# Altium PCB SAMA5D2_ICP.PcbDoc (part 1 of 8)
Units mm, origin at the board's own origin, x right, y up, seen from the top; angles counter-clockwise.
Board outline 150 x 100 mm, 6 copper layers (L1 - TOP, L2 - GND, L3 - SIG, L4 - SIG, L5 - VCC, L6 - BOT), stack 1.512 mm thick; 708 components, 597 nets, 2710 pads, 1437 vias.
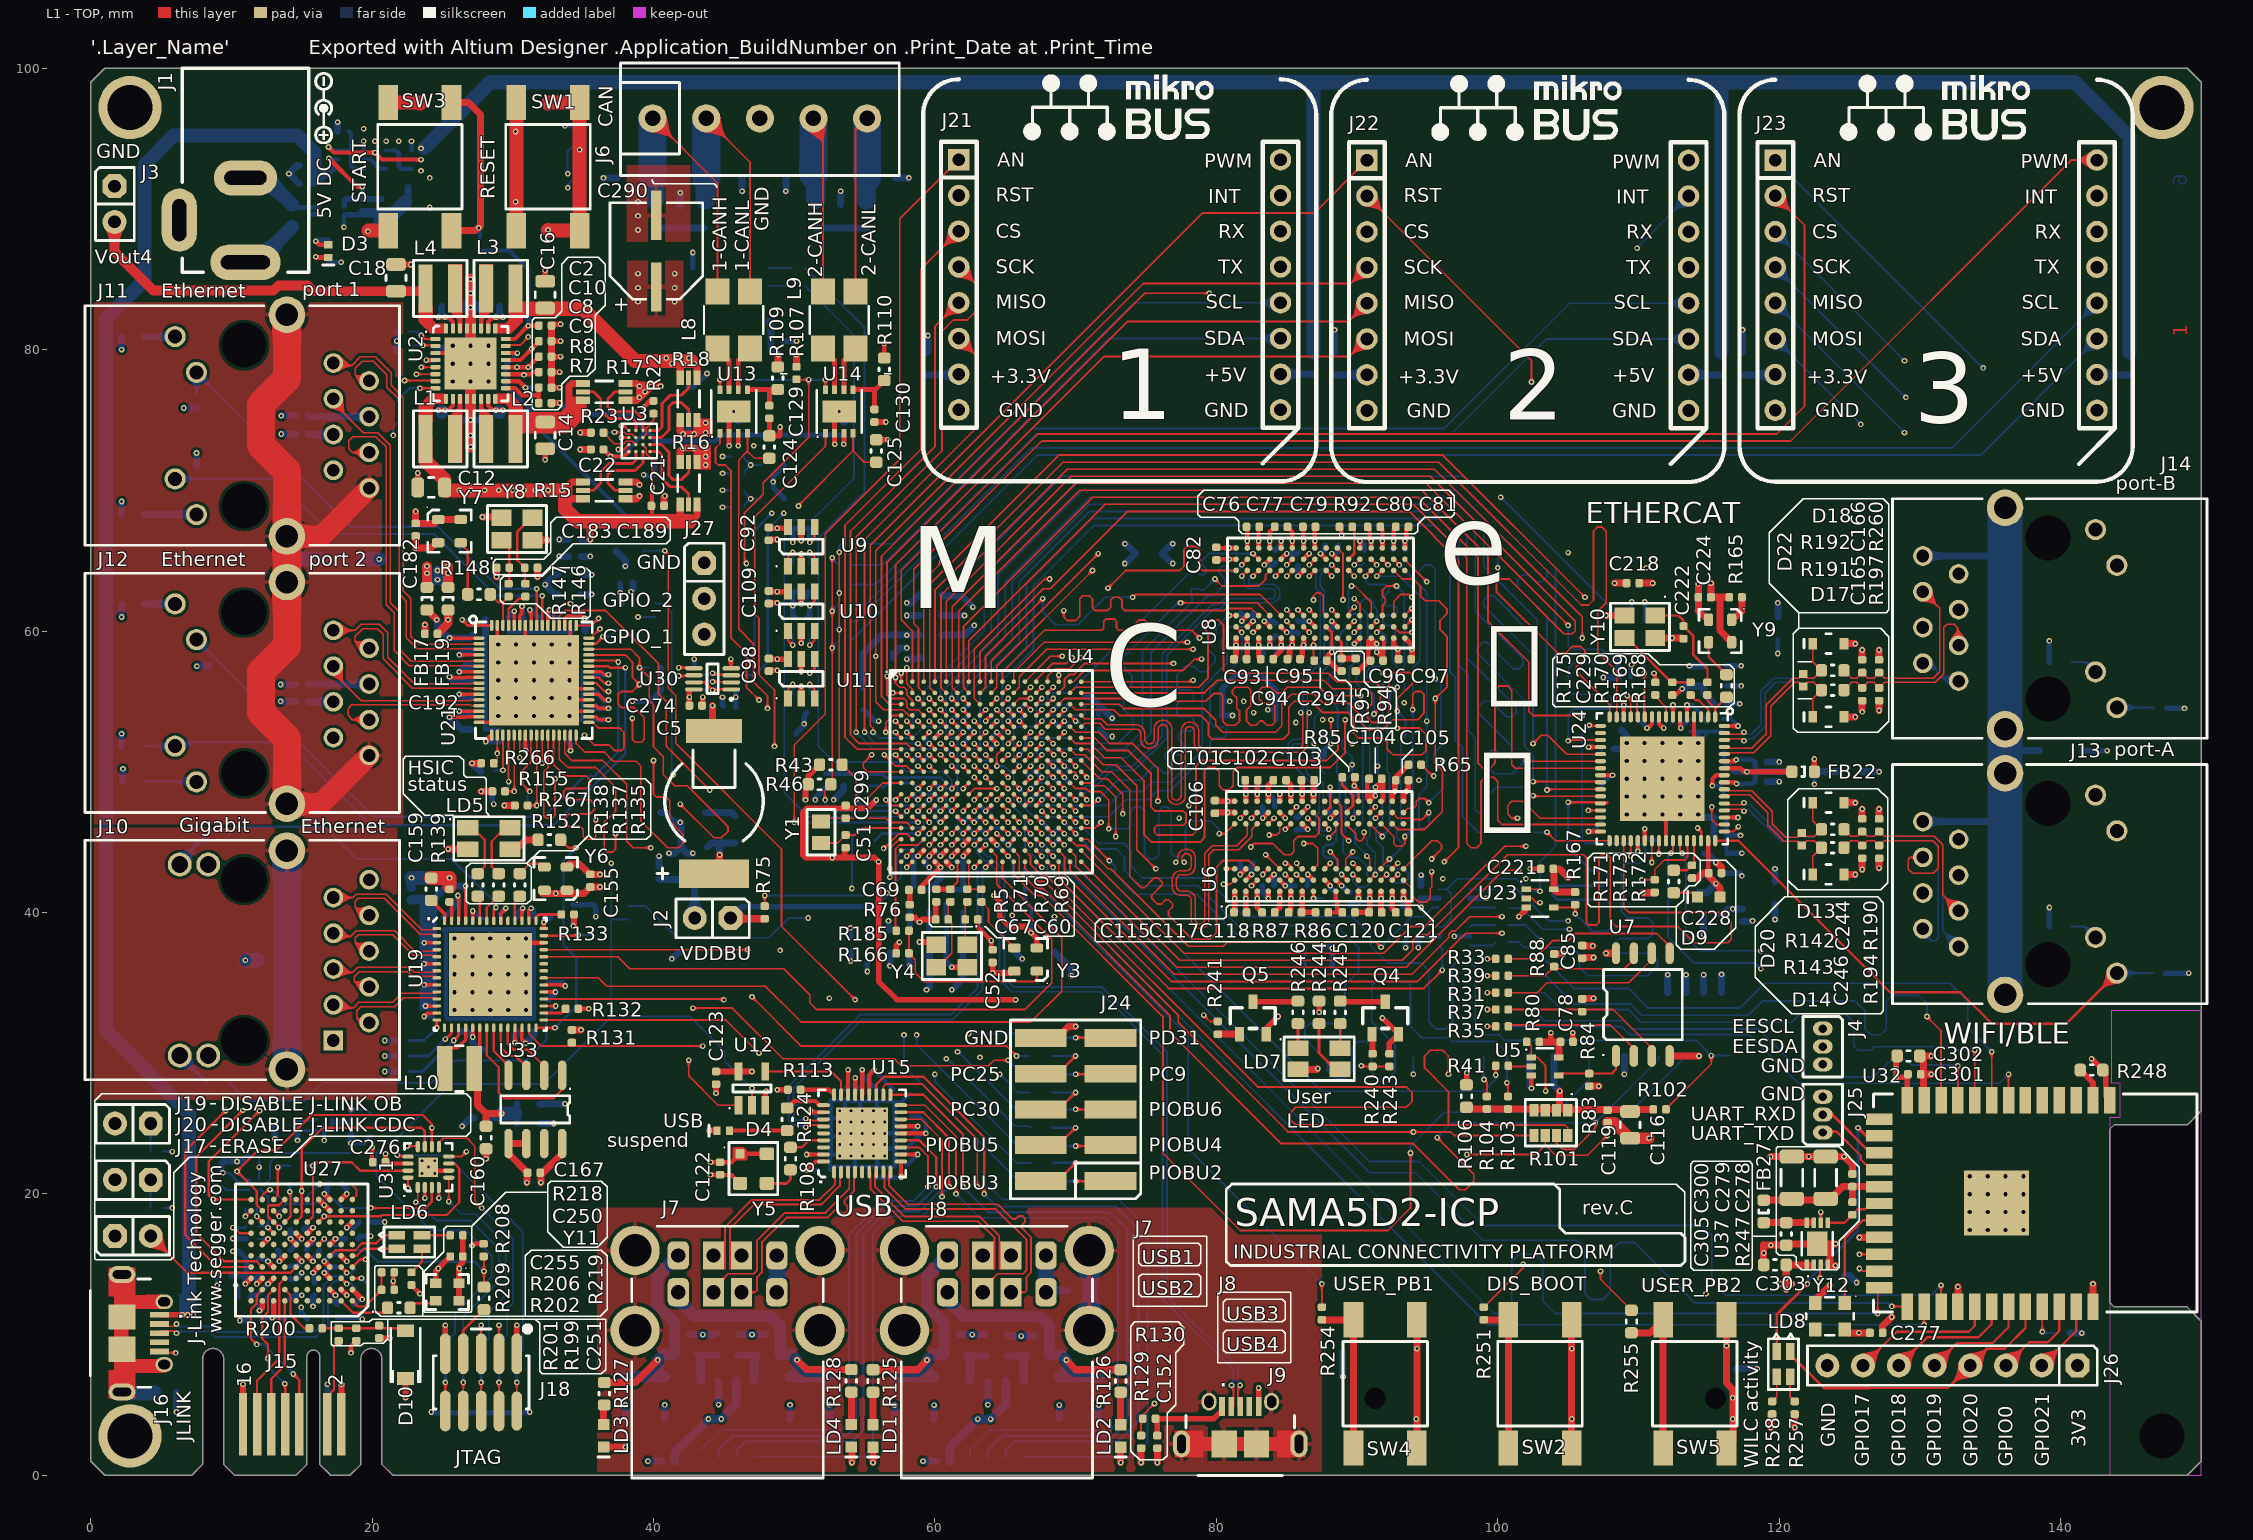
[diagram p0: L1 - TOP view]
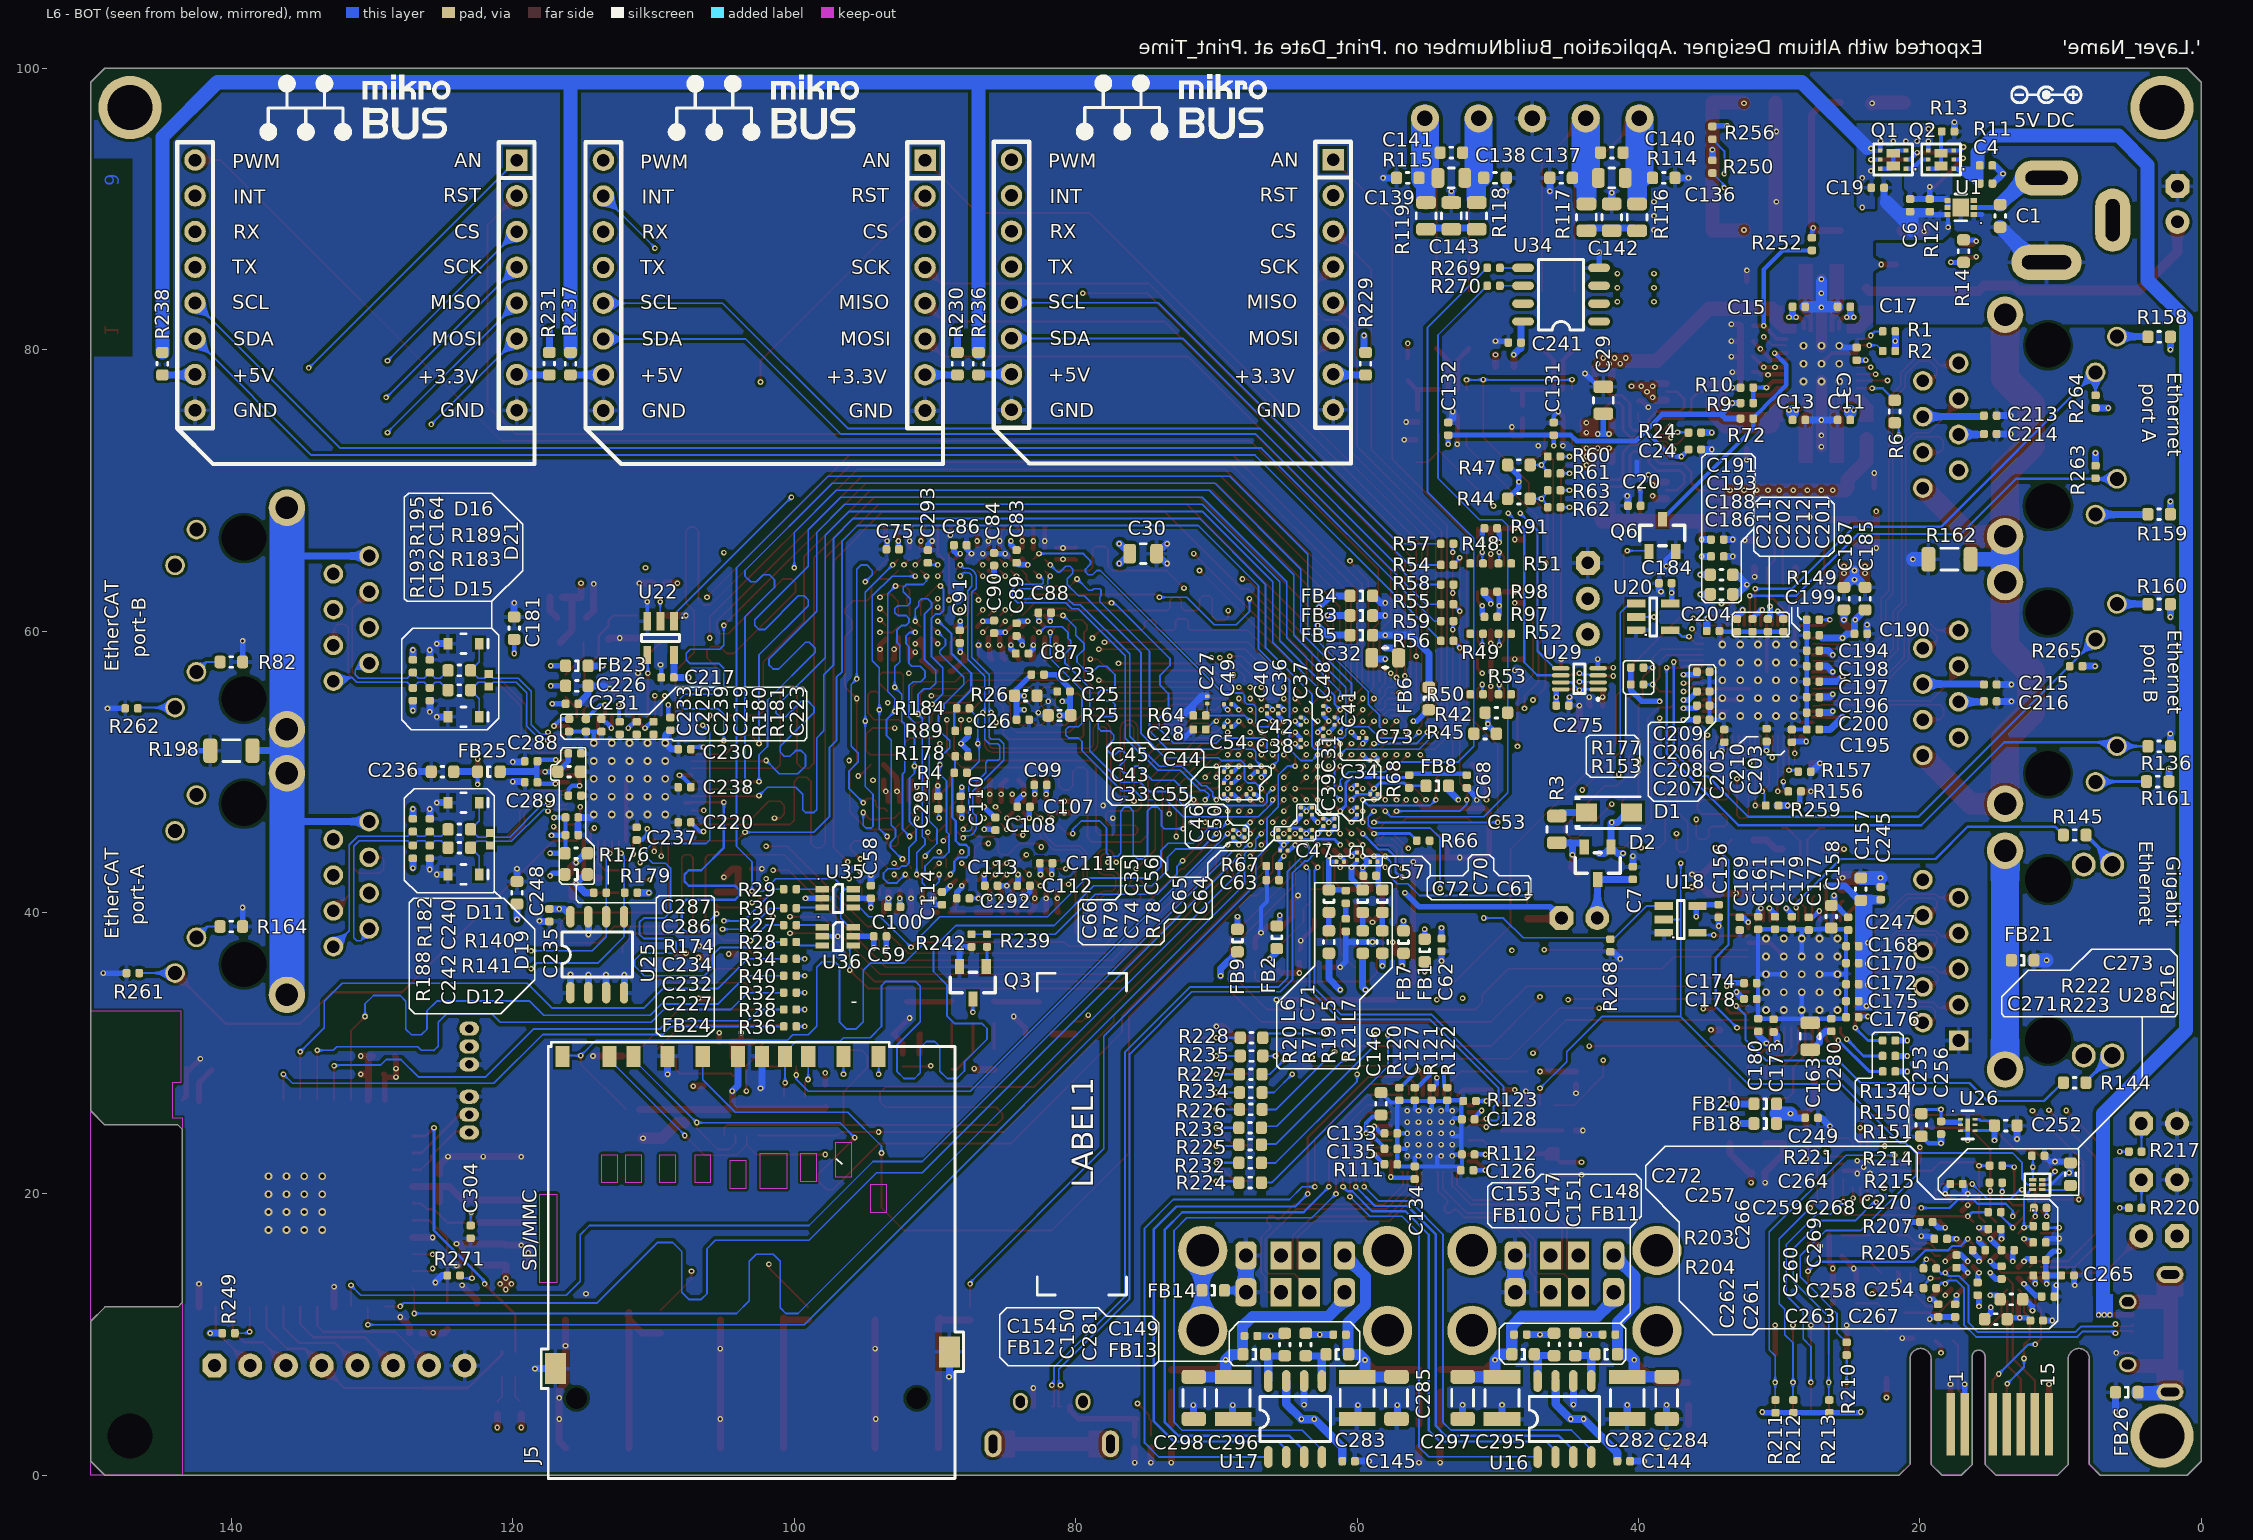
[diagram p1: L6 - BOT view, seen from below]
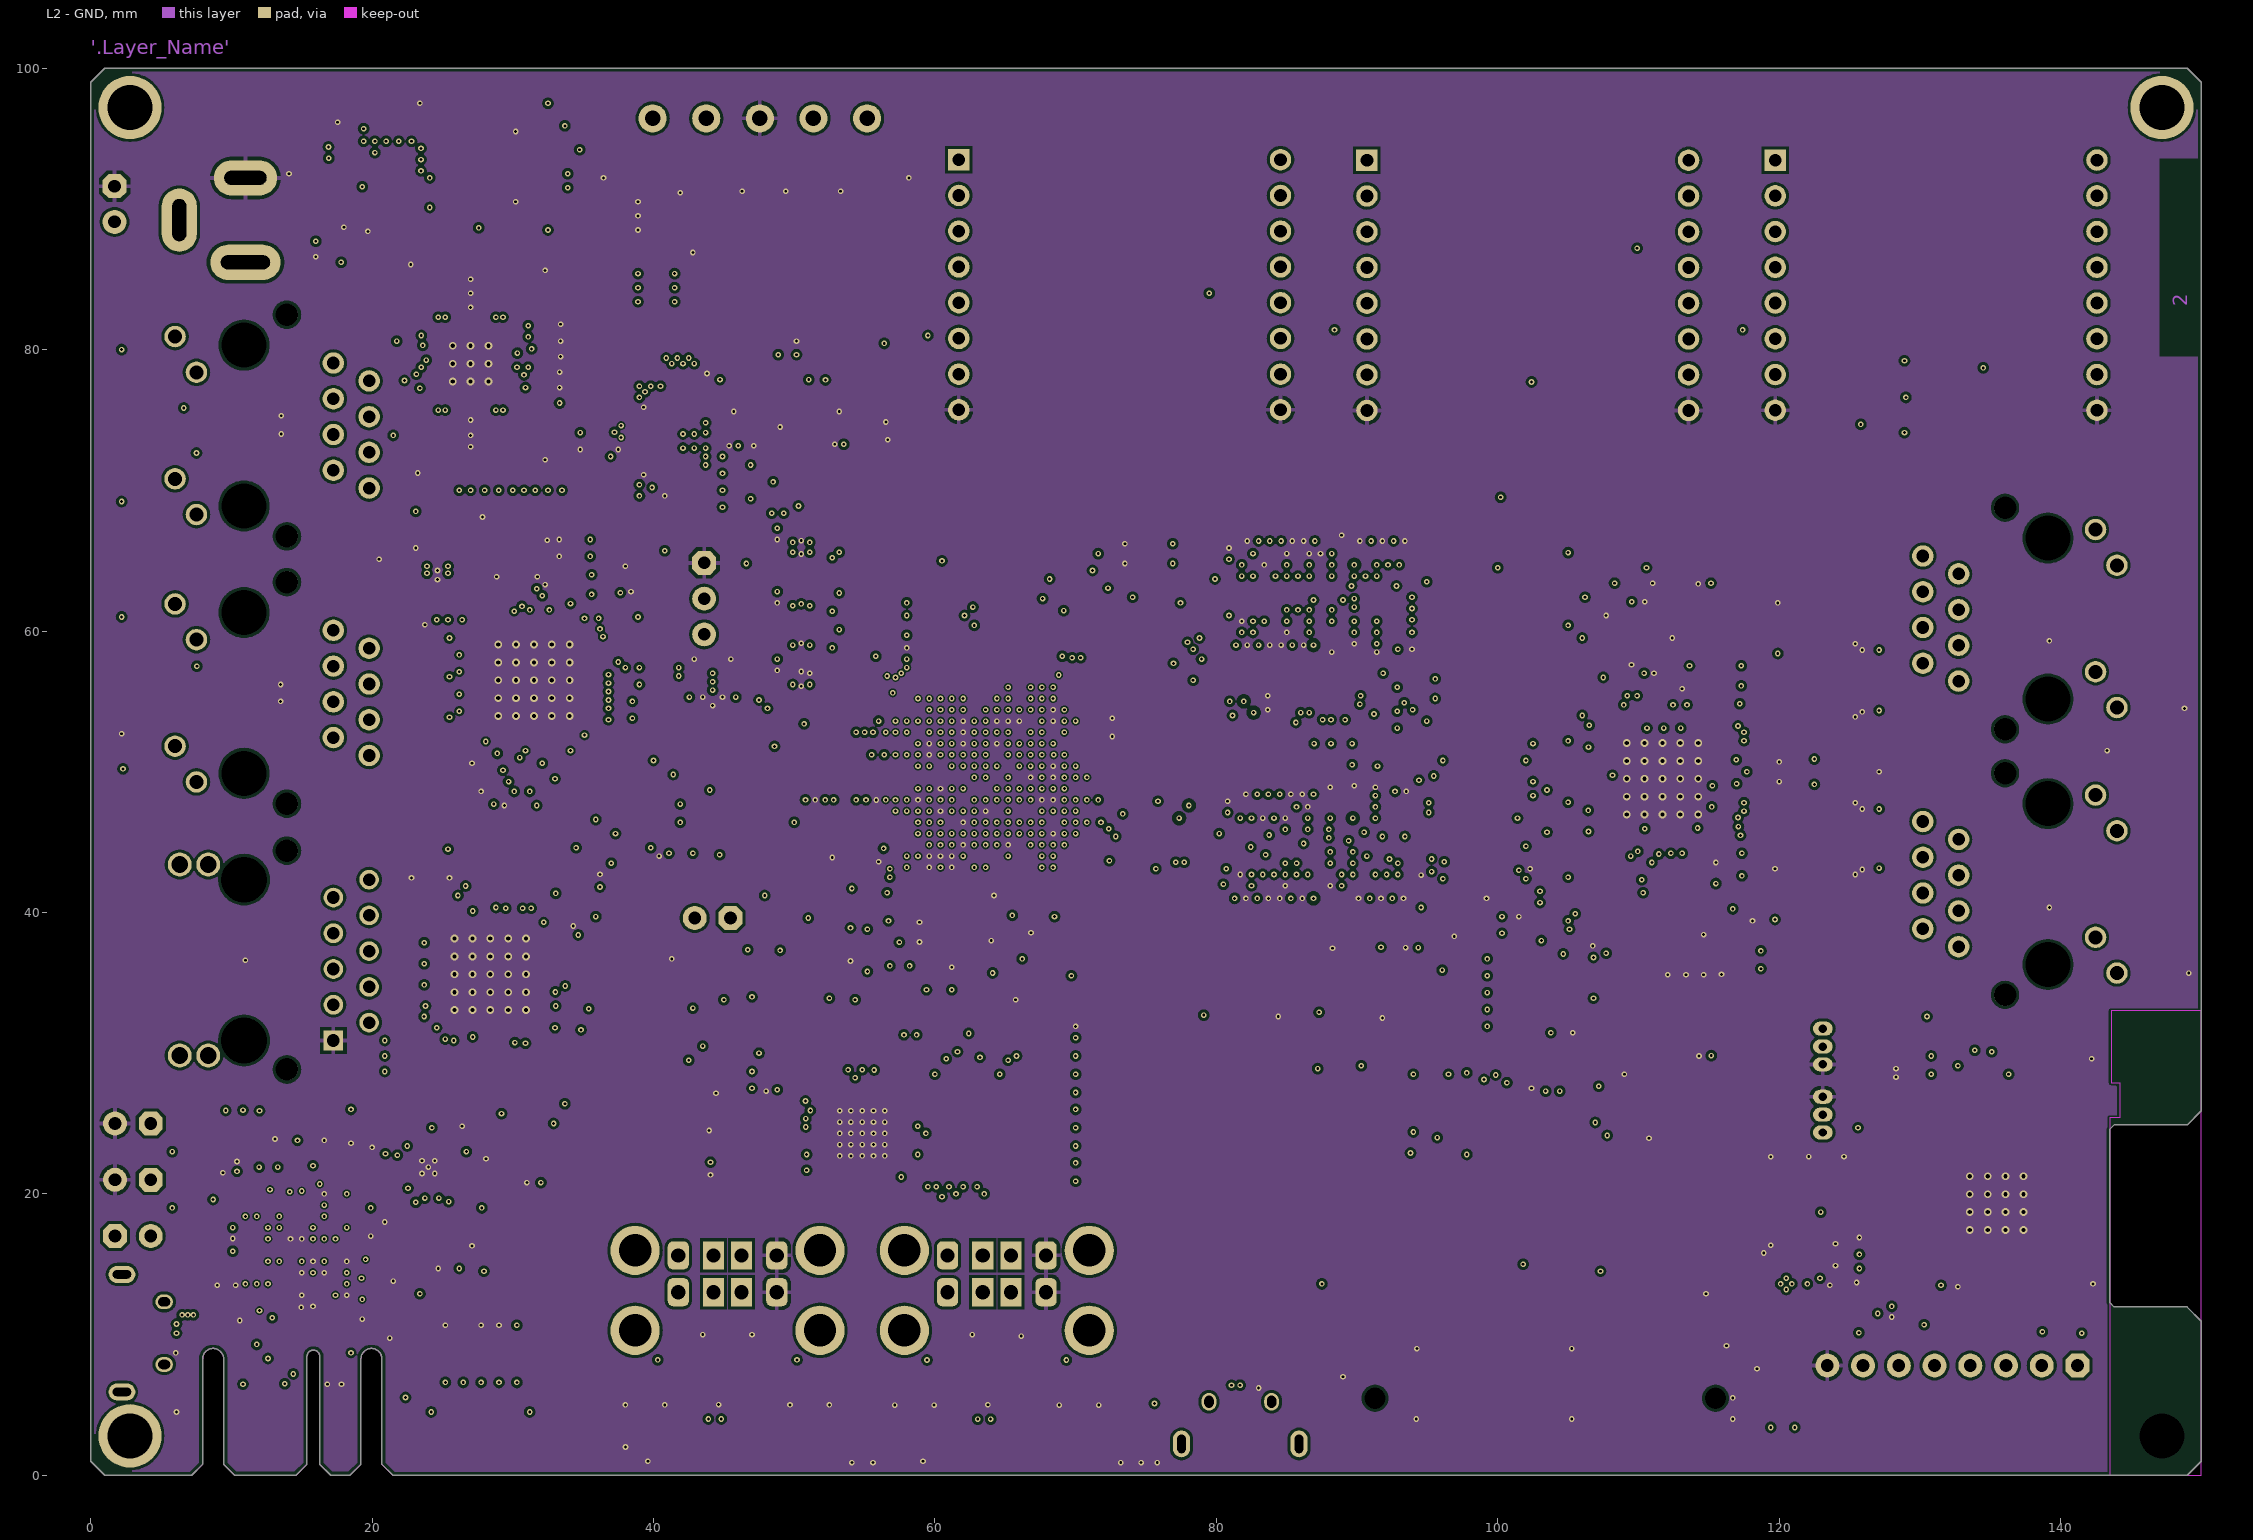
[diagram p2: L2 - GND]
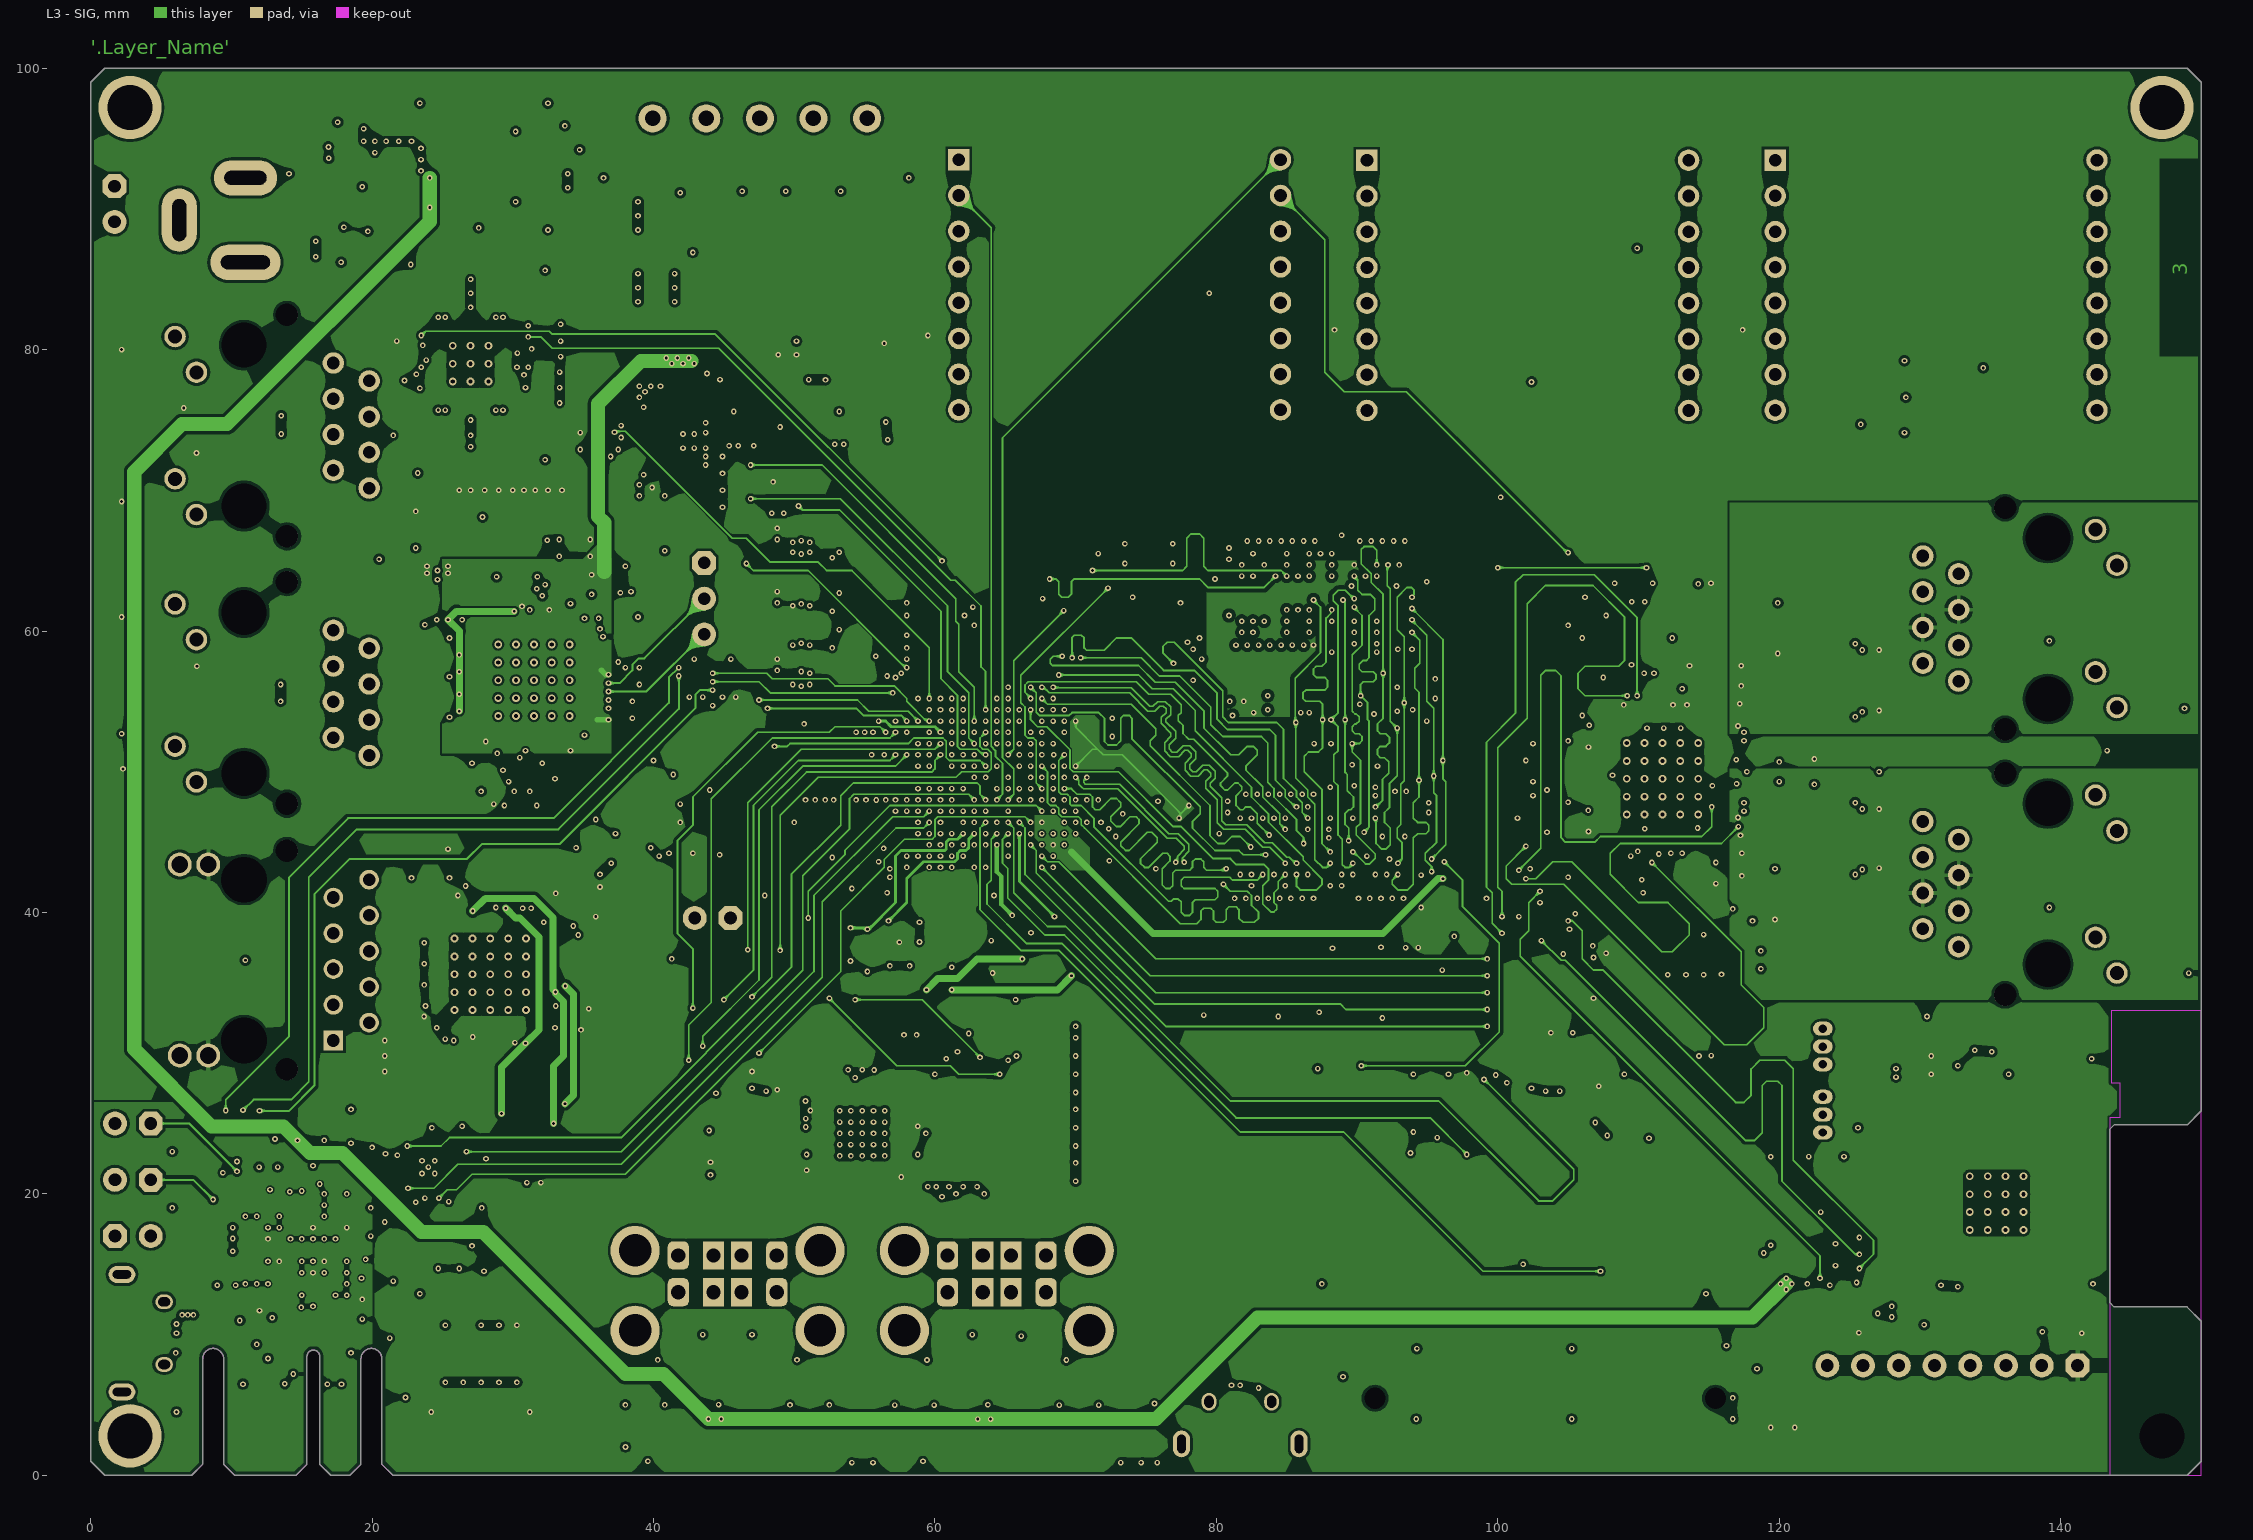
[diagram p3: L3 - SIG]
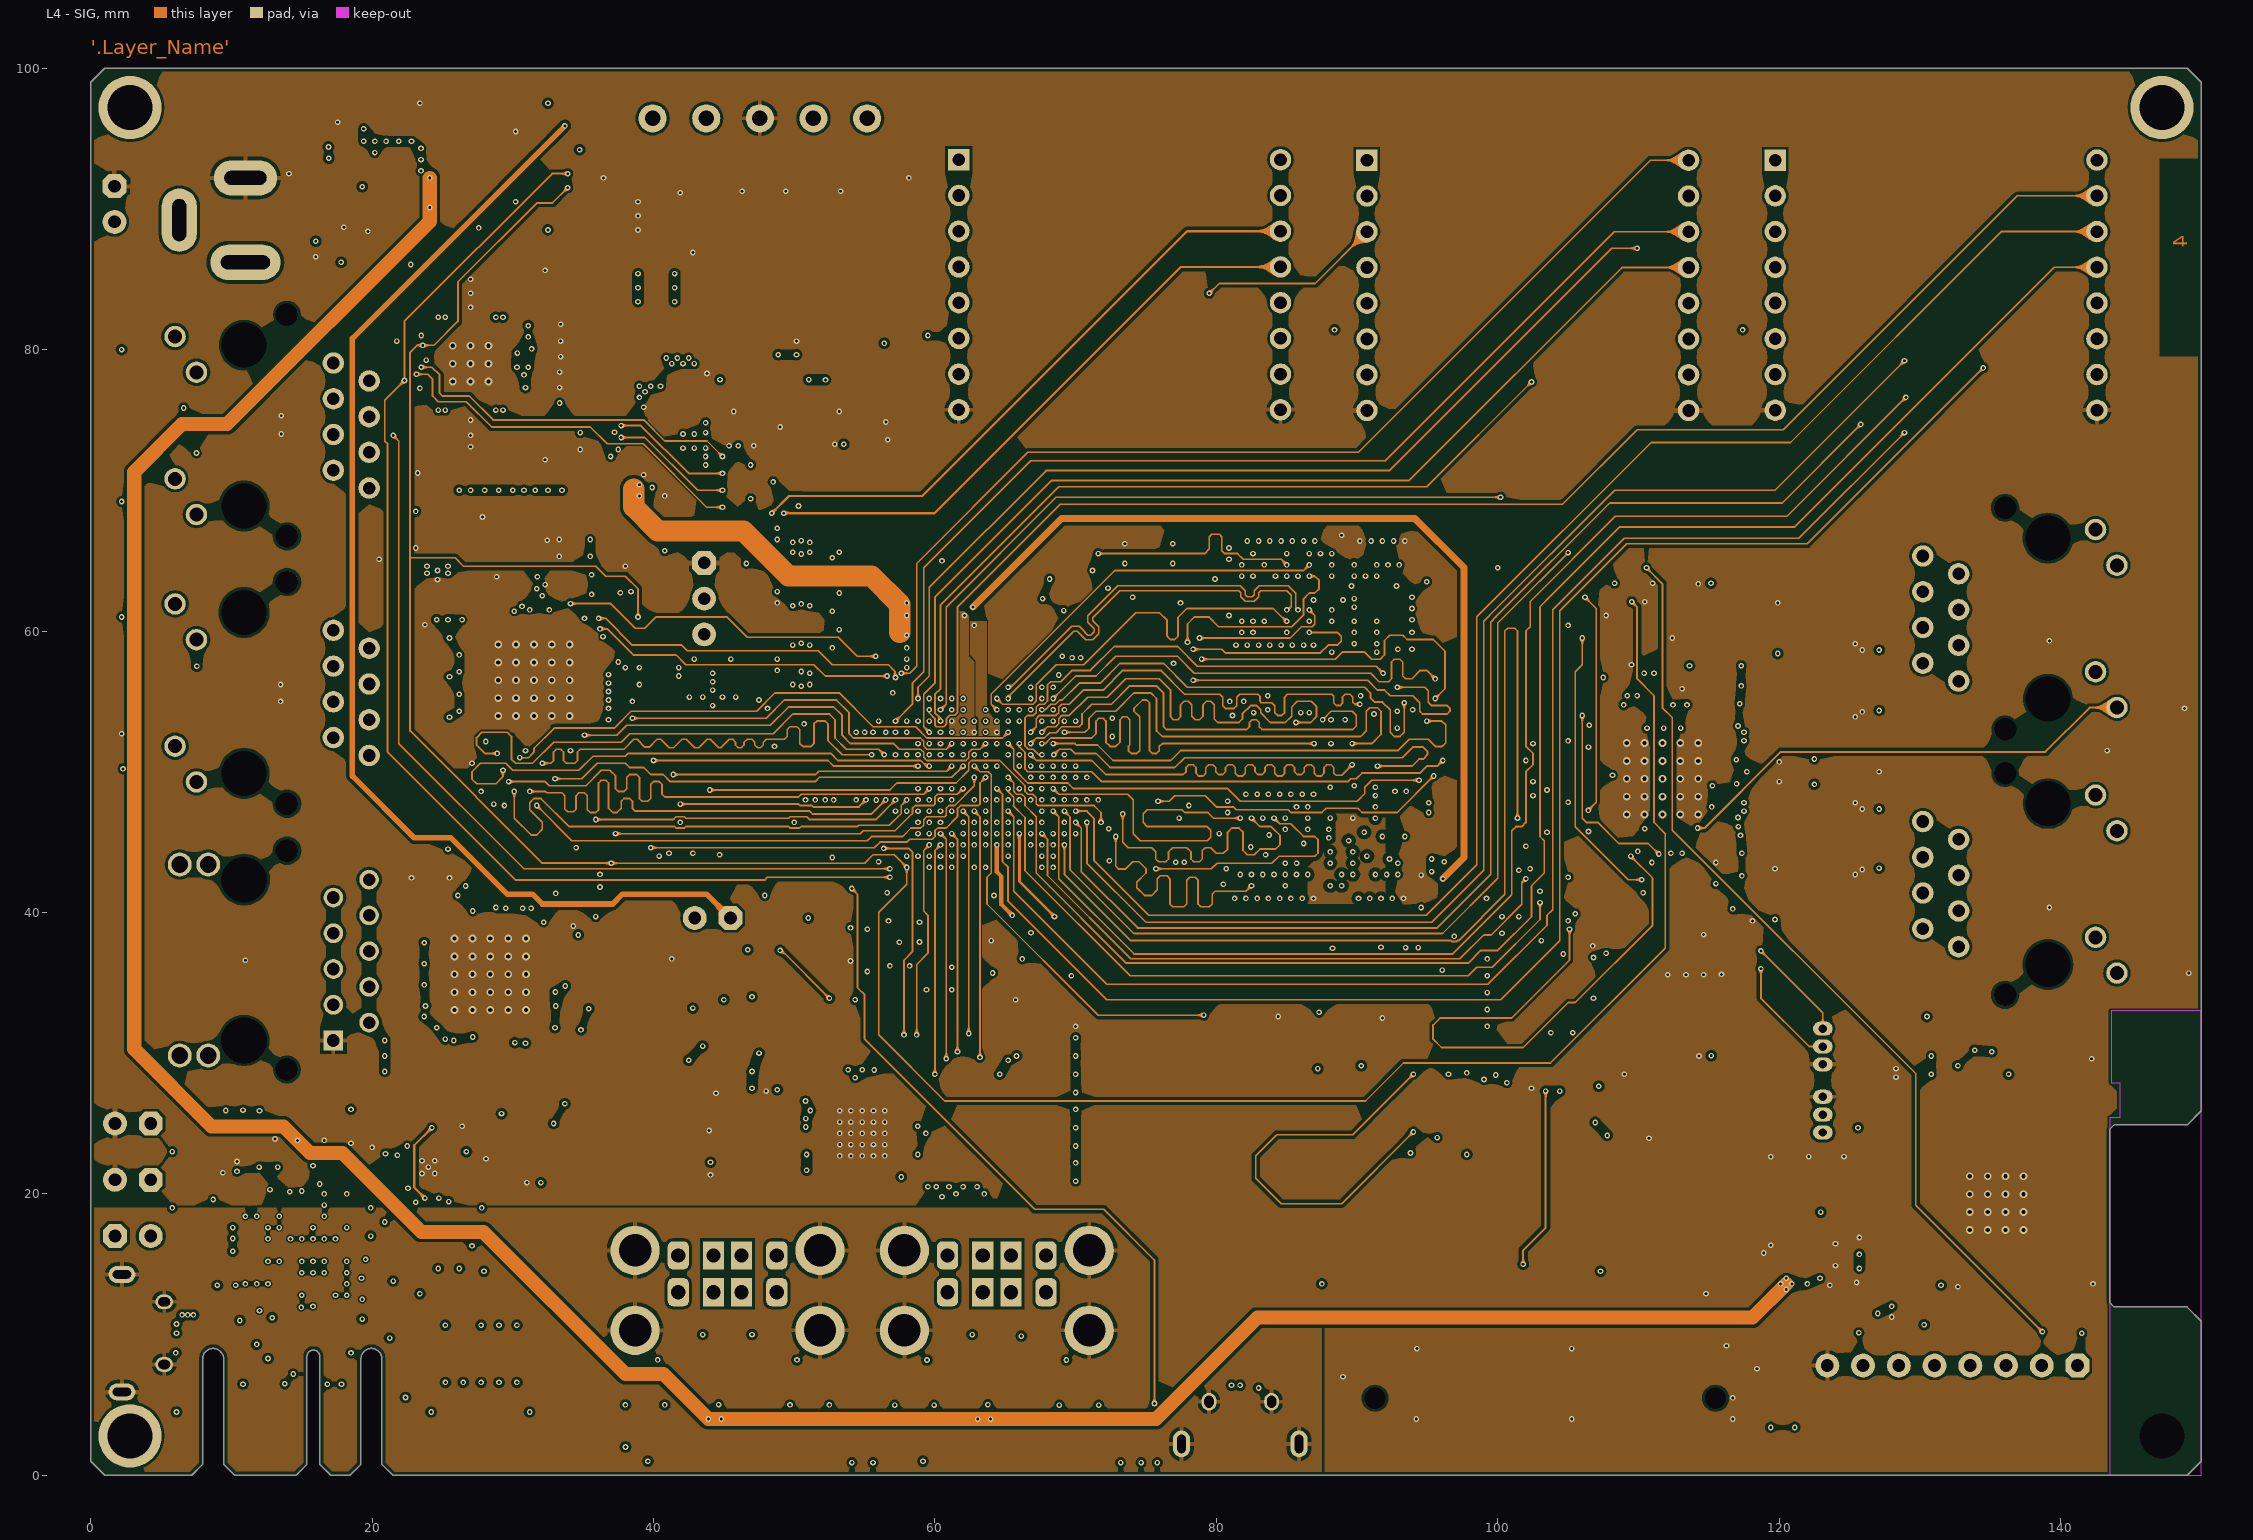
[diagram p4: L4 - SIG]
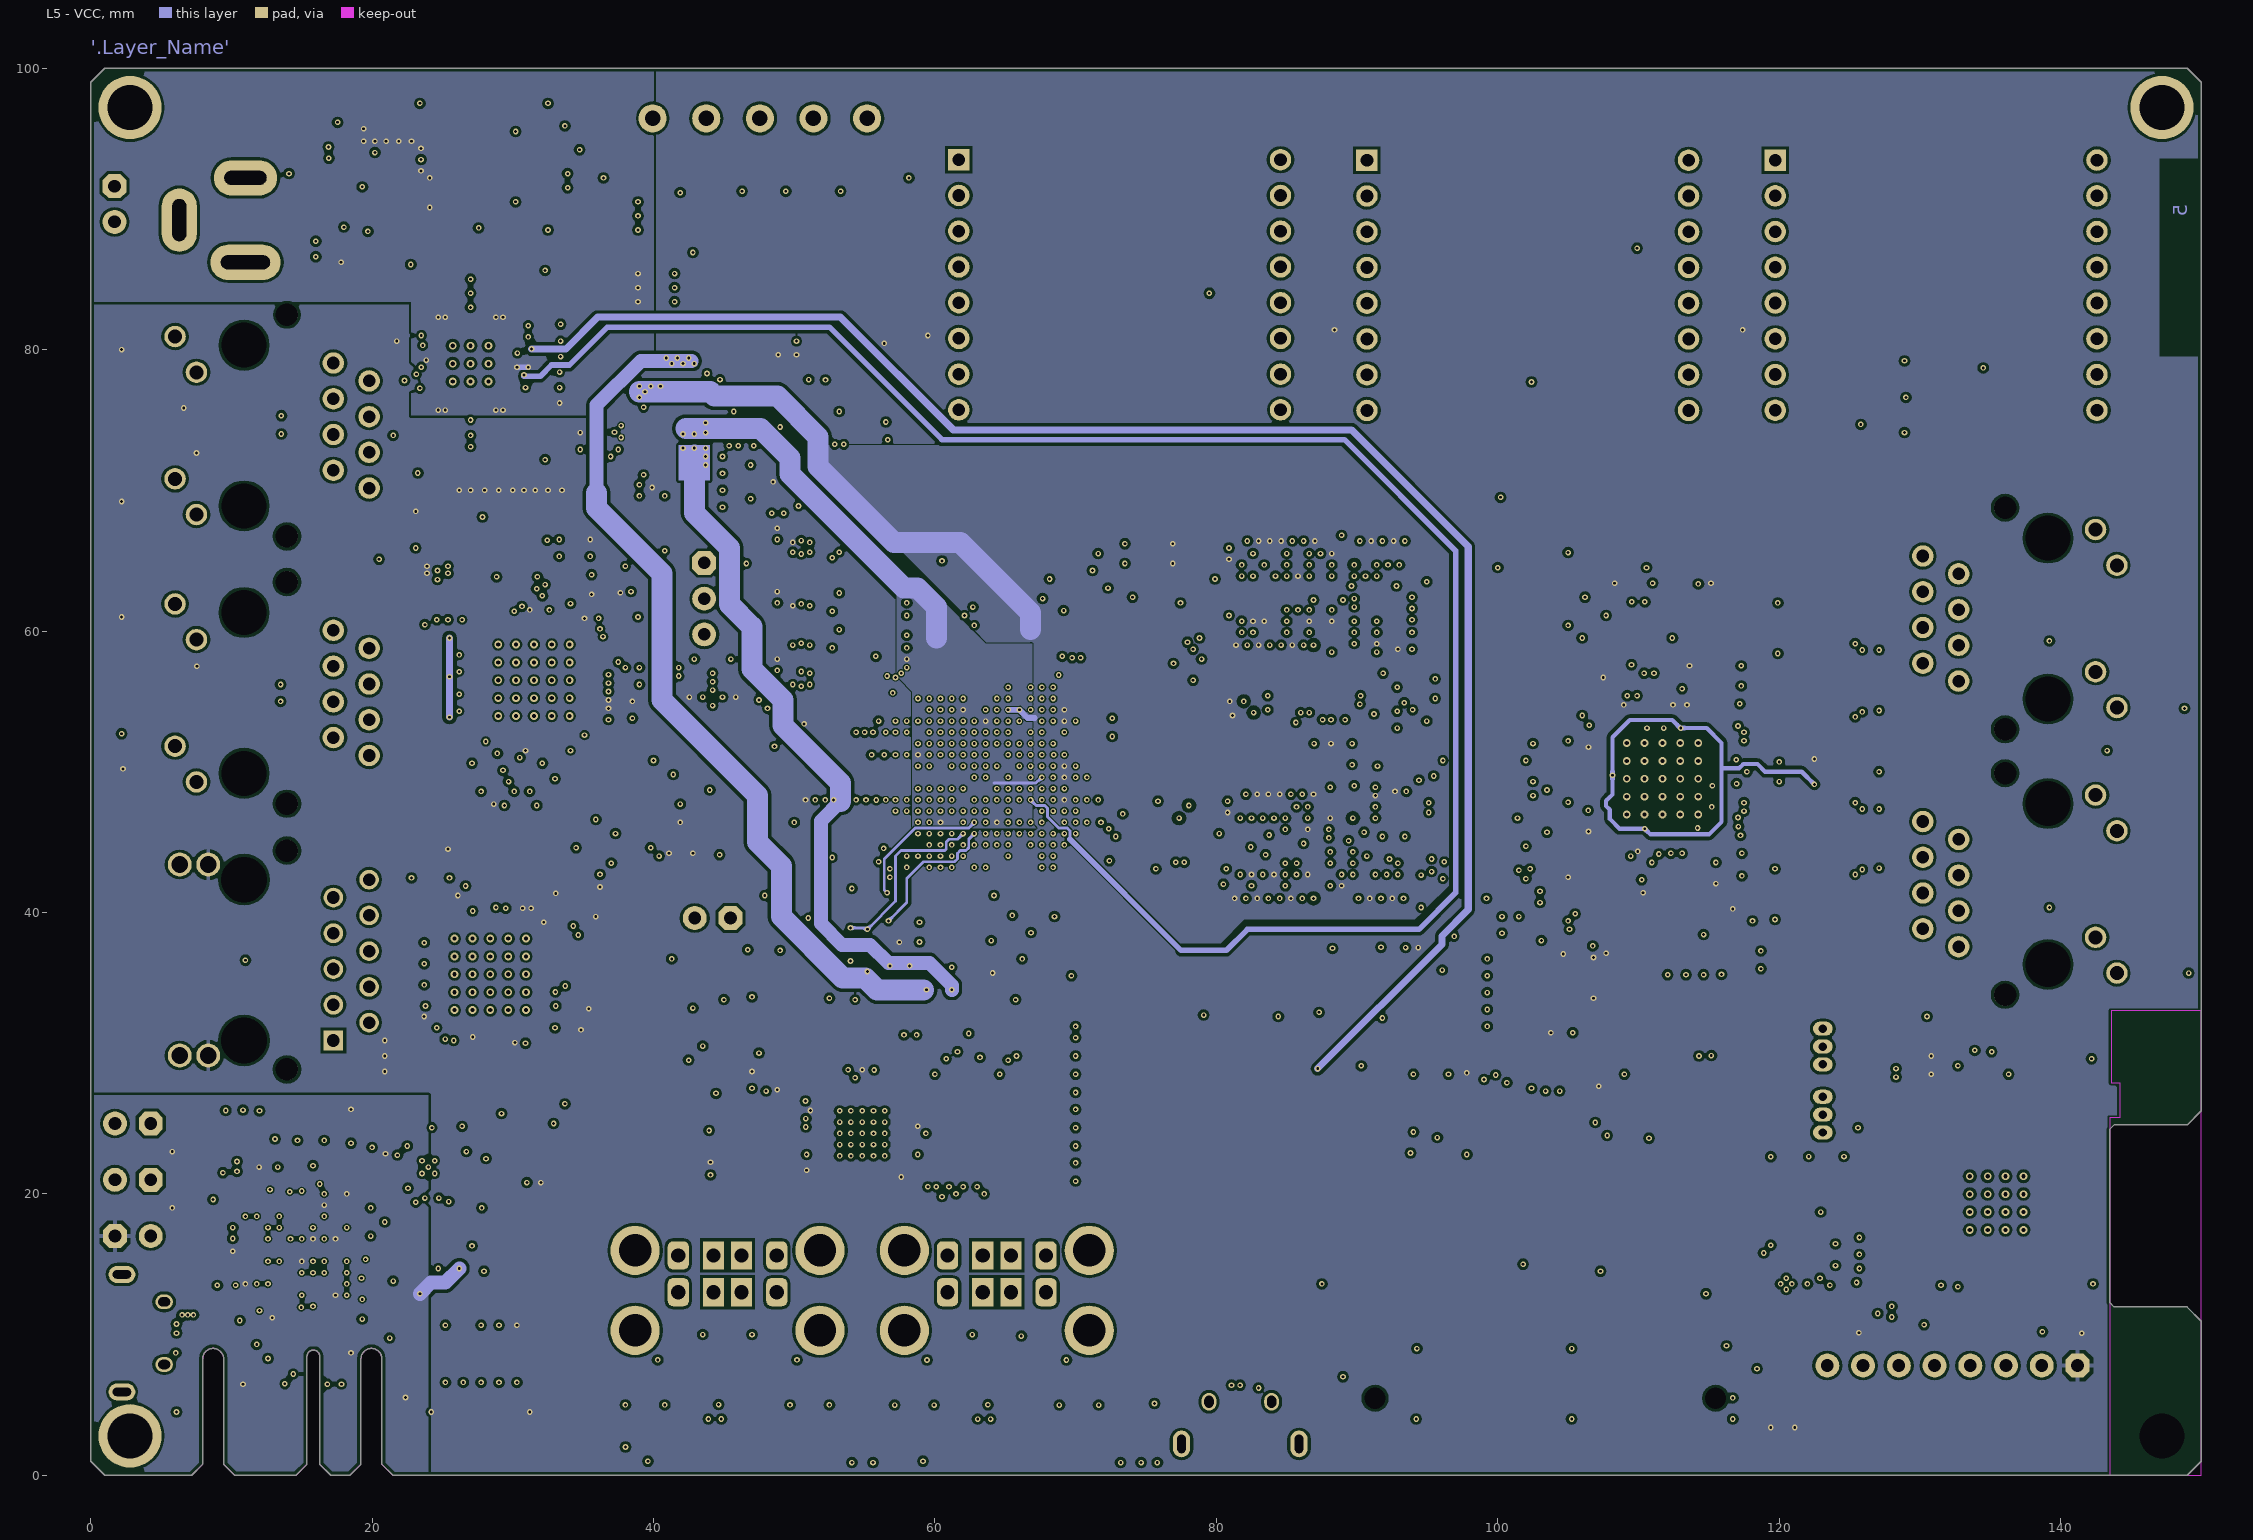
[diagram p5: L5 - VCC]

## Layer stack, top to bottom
Top Solder: solder mask 0.025, Solder Resist, Dk 3.5
L1 - TOP: signal copper 0.0356
Dielectric 1: prepreg 0.085, Prepreg, Dk 4.2
L2 - GND: signal copper 0.0178
Dielectric 2: core 0.1, FR-4, Dk 4.2
L3 - SIG: signal copper 0.0178
Dielectric 3: prepreg 1, Prepreg, Dk 4.1
L4 - SIG: signal copper 0.0178
Dielectric 4: core 0.1, FR-4, Dk 4.2
L5 - VCC: signal copper 0.0178
Dielectric 5: prepreg 0.085, Prepreg, Dk 4.2
L6 - BOT: signal copper 0.0356
Bottom Solder: solder mask 0.025, Solder Resist, Dk 3.5

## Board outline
1,0 7.18,0 7.955,0.775 7.955,8.265 cw(c8.705,8.265) 9.455,8.265 9.455,0.775 10.23,0 14.598,0 15.373,0.775 15.373,8.443 cw(c15.83,8.443) 16.287,8.443 16.287,0.775 17.062,0 18.43,0 19.205,0.775 19.205,8.265 cw(c19.955,8.265) 20.705,8.265 20.705,0.775 21.48,0 149.02,0 149,0 150,1 150,10.95 148.985,11.965 143.8,11.965 143.5,12.265 143.5,24.6 143.8,24.9 149,24.9 150,25.9 150,28 150,99 149,100 1,100 0,99 0,1

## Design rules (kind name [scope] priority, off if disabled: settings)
BoardOutlineClearance [All] p1: gap=0.25 ignorepadtopadclearanceinfootprint=FALSE
Clearance Clearance_U1 [InNet('NetC1_2') vs InNet('GND')] p1: gap=0.125 ignorepadtopadclearanceinfootprint=TRUE except(0.25: Arc-Fill Arc-Poly Arc-Region Track-Fill Track-Poly Track-Region SMDPad-Fill SMDPad-Poly SMDPad-Region THPad-Fill THPad-Poly THPad-Region Via-Fill Via-Poly Via-Region Fill-Fill Fill-Poly Fill-Region Fill-Text Poly-Poly Poly-Region Poly-Text Region-Region Region-Text)
Clearance Clearance_MPU [WithinRoom('Room_MPU') or TouchesRoom('Room_MPU')] p2: gap=0.1 ignorepadtopadclearanceinfootprint=TRUE
Clearance Clearance_DDR_REF [InNet('DDR_REF')] p3: gap=0.3 ignorepadtopadclearanceinfootprint=TRUE except(0.165: SMDPad-Via; 0.2: Arc-SMDPad Arc-Via Track-SMDPad Track-Via; 0.25: SMDPad-Hole)
Clearance Clearance_DDR3_CHIP [InComponent('U8') or InComponent('U6') vs IsVia or IsTrack] p4: gap=0.2 ignorepadtopadclearanceinfootprint=TRUE except(0.1: Arc-SMDPad Track-SMDPad; 0.165: SMDPad-Via)
Clearance Clearance_USB_HSIC [WithinRoom('Room_USB_HSIC') or TouchesRoom('Room_USB_HSIC')] p5: gap=0.175 ignorepadtopadclearanceinfootprint=TRUE
Clearance Clearance_HSIC [InNet('HSIC_DATA') or InNet('HSIC_STROBE')] p6: gap=0.413 ignorepadtopadclearanceinfootprint=TRUE
Clearance Clearance-U1 [InComponent('U1')] p7: gap=0.14 ignorepadtopadclearanceinfootprint=TRUE
Clearance Clearance-KSZ8563RNX [WithinRoom('Room_KSZ8563RNX')] p8: gap=0.15 ignorepadtopadclearanceinfootprint=TRUE except(0.1: Arc-Via Track-Via)
Clearance Clearance-U28 [InComponent('U28')] p9: gap=0.135 ignorepadtopadclearanceinfootprint=TRUE
Clearance Clearance_3U [WithinRoom('Room_3U')] p10: gap=0.1 ignorepadtopadclearanceinfootprint=TRUE
Clearance Clearance_PAC1934 [WithinRoom('Room_PAC1934') or TouchesRoom('Room_PAC1934')] p11: gap=0.1 ignorepadtopadclearanceinfootprint=TRUE
Clearance Clearance_EtherCAT_SIG [InNetClass('EtherCAT_SIG')] p12: gap=0.2 ignorepadtopadclearanceinfootprint=TRUE except(0.1: Arc-Via Track-Via SMDPad-Via; 0.135: Arc-SMDPad Track-SMDPad; 0.15: Arc-Arc Arc-Track Track-Track Via-Via)
Clearance Clearance_CON_EtherCAT [InComponent('J13') or InComponent('J14')] p13: gap=0.19 ignorepadtopadclearanceinfootprint=TRUE
Clearance Clearance-SenseRes [InComponent('R15') or  InComponent('R16') or InComponent('R17') or InComponent('R18')] p14: gap=0.125 ignorepadtopadclearanceinfootprint=TRUE
Clearance Clearance_PadToVia [IsPad and not InPadClass('PAD with VIA') vs IsVia] p15: gap=0.1 ignorepadtopadclearanceinfootprint=TRUE
Clearance [All] p16: gap=0.2 ignorepadtopadclearanceinfootprint=TRUE except(0.1: Arc-Via Track-Via; 0.25: Arc-Poly Track-Poly)
ComponentClearance ComponentClearance_ignore [HasFootprint('NET_TIE_0.5mm')] p1: gap=0 collisioncheckmode=3 verticalgap=0 showdistances=FALSE
ComponentClearance [All] p2: gap=0.2 collisioncheckmode=3 verticalgap=0.2 showdistances=FALSE
DiffPairsRouting DIFF90 [InDifferentialPairClass('DIFF90')] p1: maxlimit=0.254 minlimit=0.15 mostfreqgap=0.254 toplayer_prefgap=0.2 toplayer_minwidth=0.125 toplayer_maxwidth=0.165 toplayer_prefwidth=0.135 midlayer1_minwidth=0.381 midlayer1_maxwidth=0.381 midlayer1_prefwidth=0.381 midlayer2_minwidth=0.381 midlayer2_maxwidth=0.381 midlayer2_prefwidth=0.381 midlayer3_minwidth=0.381 midlayer3_maxwidth=0.381 midlayer3_prefwidth=0.381 midlayer4_minwidth=0.381 midlayer4_maxwidth=0.381 midlayer4_prefwidth=0.381 bottomlayer_prefgap=0.2 bottomlayer_minwidth=0.125 bottomlayer_maxwidth=0.165 bottomlayer_prefwidth=0.135 maxuncoupledlength=12.7
DiffPairsRouting DIFF100 [InDifferentialPairClass('DIFF100')] p2: maxlimit=0.254 minlimit=0.175 mostfreqgap=0.225 toplayer_prefgap=0.203 toplayer_minwidth=0.1 toplayer_maxwidth=0.102 toplayer_prefwidth=0.102 midlayer1_minwidth=0.381 midlayer1_maxwidth=0.381 midlayer1_prefwidth=0.381 midlayer2_minwidth=0.1 midlayer2_maxwidth=0.102 midlayer2_prefwidth=0.102 midlayer3_minwidth=0.1 midlayer3_maxwidth=0.102 midlayer3_prefwidth=0.102 midlayer4_minwidth=0.381 midlayer4_maxwidth=0.381 midlayer4_prefwidth=0.381 bottomlayer_prefgap=0.203 bottomlayer_minwidth=0.1 bottomlayer_maxwidth=0.102 bottomlayer_prefwidth=0.102 maxuncoupledlength=12.7
FabricationTestPointUsage TestPointUsage [All] p1: valid=0 allowmultiple=FALSE
FabricationTestpoint Testpoint [All] p1: side=3 testpointundercomponent=TRUE minsize=1.016 maxsize=2.54 preferedsize=1.524 minholesize=0 maxholesize=1.016 preferedholesize=0.813 testpointgrid=0.025 allowsidetop=TRUE allowsidebottom=TRUE usegrid=TRUE gridtolerance=0
HoleSize [All] p1: absolutevalues=TRUE maxlimit=6 minlimit=0.2 maxpercent=80.000 minpercent=20.000
HoleToHoleClearance [All] p1: gap=0.3 allowstackedmicrovias=FALSE
MatchedLengths "Schematic Matched Net Lengths_3" [InNetClass('Ethernet_SIG')] p1 off: tolerance=0.254 checknetsindiffpair=FALSE checkdiffpairvsdiffpair=TRUE checkxsignals=TRUE checkothers=TRUE
MatchedLengths "Schematic Matched Net Lengths_2" [InNetClass('DIFF100')] p2: tolerance=0.254 checknetsindiffpair=TRUE checkdiffpairvsdiffpair=FALSE checkxsignals=FALSE checkothers=FALSE
MatchedLengths "Schematic Matched Net Lengths" [InNetClass('DIFF90')] p3: tolerance=0.254 checknetsindiffpair=TRUE checkdiffpairvsdiffpair=FALSE checkxsignals=FALSE checkothers=FALSE
MatchedLengths xEtherCAT [InxSignalClass('xEtherCAT')] p4: tolerance=0.254 checknetsindiffpair=FALSE checkdiffpairvsdiffpair=TRUE checkxsignals=TRUE checkothers=TRUE
MatchedLengths xSDMMC [InxSignalClass('xSDMMC')] p5: tolerance=0.254 checknetsindiffpair=FALSE checkdiffpairvsdiffpair=TRUE checkxsignals=TRUE checkothers=TRUE
MatchedLengths xEtherSwitch [InxSignalClass('xEtherSwitch')] p6: tolerance=0.254 checknetsindiffpair=FALSE checkdiffpairvsdiffpair=TRUE checkxsignals=TRUE checkothers=TRUE
MatchedLengths DDR_ADDR [InxSignalClass('ADDR_PP1') OR InxSignalClass('ADDR_PP1')] p7: tolerance=0.254 checknetsindiffpair=FALSE checkdiffpairvsdiffpair=TRUE checkxsignals=TRUE checkothers=TRUE
MatchedLengths DDR_DATA_BL3 [InxSignalClass('DATA_BL3')] p8: tolerance=0.254 checknetsindiffpair=FALSE checkdiffpairvsdiffpair=TRUE checkxsignals=TRUE checkothers=TRUE
MatchedLengths DDR_DATA_BL2 [InxSignalClass('DATA_BL2')] p9: tolerance=0.254 checknetsindiffpair=FALSE checkdiffpairvsdiffpair=TRUE checkxsignals=TRUE checkothers=TRUE
MatchedLengths DDR_DATA_BL1 [InxSignalClass('DATA_BL1')] p10: tolerance=0.254 checknetsindiffpair=FALSE checkdiffpairvsdiffpair=TRUE checkxsignals=TRUE checkothers=TRUE
MatchedLengths DDR_DATA_BL0 [InxSignalClass('DATA_BL0')] p11: tolerance=0.254 checknetsindiffpair=FALSE checkdiffpairvsdiffpair=TRUE checkxsignals=TRUE checkothers=TRUE
MinimumAnnularRing [All] p1: minimumring=0.1
MinimumSolderMaskSliver [All and Not HasFootprint('RES_C_CAV_0603x4') and Not HasFootprint('DFN-6_2x1.6_EP0.4x0.35')] p1: minsoldermaskwidth=0.1
PasteMaskExpansion "Remove Paste from DNP" [IsPad and HasCompParameterValue('Populated','DNP')] p1: expansion=-10
PasteMaskExpansion [All] p2: expansion=0
PlaneClearance [All] p1: clearance=0.25
PlaneConnect [All] p1: pad.planeconnectstyle=Relief pad.reliefexpansion=0.3 pad.reliefentries=4 pad.reliefconductorwidth=0.25 pad.reliefairgap=0.25 via.planeconnectstyle=Direct via.reliefexpansion=0.3 via.reliefentries=4 via.reliefconductorwidth=0.25 via.reliefairgap=0.25
PolygonConnect [All] p1: thpad.connectstyle=Relief thpad.reliefconductorwidth=0.3 thpad.reliefentries=4 thpad.polygonreliefangle="90 Angle" thpad.airgapwidth=0.25 smdpad.connectstyle=Relief smdpad.reliefconductorwidth=0.3 smdpad.reliefentries=4 smdpad.polygonreliefangle="90 Angle" smdpad.airgapwidth=0.25 via.connectstyle=Direct via.reliefconductorwidth=0.3 via.reliefentries=4 via.polygonreliefangle="90 Angle" via.airgapwidth=0.25
RoomDefinition Room_USB_HSIC [All] p1: confinementstyle=ConfineIn formatcopy=TRUE lockcomponents=FALSE outline 24.1,31.2 32.7,31.2 32.7,39.9 24.1,39.9
RoomDefinition Room_KSZ8563RNX [InComponent('U21')] p2: confinementstyle=ConfineIn formatcopy=TRUE lockcomponents=FALSE outline 26,51.3 36.7,51.3 36.7,61.7 26,61.7
RoomDefinition Room_3U [All] p3: confinementstyle=ConfineIn formatcopy=TRUE lockcomponents=FALSE outline 19.8,20.8 10.2,20.8 10.2,11.2 19.8,11.2
RoomDefinition Room_MPU [All] p4: confinementstyle=ConfineIn formatcopy=TRUE lockcomponents=FALSE outline 56.5,57.5 71.5,57.5 71.5,42.5 56.5,42.5
RoomDefinition Room_PAC1934 [InComponent('U3')] p5: confinementstyle=ConfineIn formatcopy=TRUE lockcomponents=TRUE outline 37.7,74.8 40.3,74.8 40.3,72.2 37.7,72.2
RoutingCorners [All] p1: cornerstyle=45-Degree minsetback=2.5 maxsetback=2.5
RoutingVias [All] p1: holewidth=0.4 width=0.8 viastyle="Through Hole" minholewidth=0.2 minwidth=0.4 maxholewidth=1.6 maxwidth=2.5
SMDToCorner [All] p1: distance=39370
SilkToSilkClearance [All] p1: silktosilkclearance=0.15
SilkToSolderMaskClearance SilkscreenOverComponentPads [IsPad] p1: minsilkscreentomaskgap=0.2 clearancetoexposedcopper=TRUE
SolderMaskExpansion [All] p1: expansion=0.05
Width [All] p1: maxlimit=7 minlimit=0.1 preferedwidth=0.125
17 further rules are at their usual default settings.

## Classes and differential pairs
differential pair class DIFF90: HHSA HHSB USBD1 USBD2 USBD3 USBD4
net class DIFF90: HHSA_n HHSA_p HHSB_n HHSB_p USBD1_n USBD1_p USBD2_n USBD2_p USBD3_n USBD3_p USBD4_n USBD4_p
differential pair class DIFF100: DDR_CLK DDR_DQS0 DDR_DQS1 DDR_DQS2 DDR_DQS3 RX1 RX2 rxa rxa1 rxb rxb1 TR0 TR1 TR2 TR3 TX1 TX2 txa txa1 txb txb1
net class DIFF100: DDR_CLK_N DDR_CLK_P DDR_DQS0_N DDR_DQS0_P DDR_DQS1_N DDR_DQS1_P DDR_DQS2_N DDR_DQS2_P DDR_DQS3_N DDR_DQS3_P RX1_N RX1_P RX2_N RX2_P rxa1_n rxa1_p rxa_n rxa_p rxb1_n rxb1_p rxb_n rxb_p TR0_N TR0_P TR1_N TR1_P TR2_N TR2_P TR3_N TR3_P TX1_N TX1_P TX2_N TX2_P txa1_n txa1_p txa_n txa_p txb1_n txb1_p txb_n txb_p
net class Ethernet_SIG: PD1 PD2 PD5 PD6 PD7 PD8 PD9 PD10 PD11 PD12 PD13 PD14 PD15 PD16
net class EtherCAT_SIG: PA22_D0 PA23 PA24 PA25 PA26 PA27 PA28_D6 PA29 PA30 PB2 PB3 PB4 PB5 PB6 PB7 PB8 PB9 PB10 PB12 PB13 PB14 PB15 PC6_NCS1
net class WILC300_SIG: NetU32_3 NetU32_4 NetU32_5 NetU32_6 NetU32_14 NetY12_3 PA18 PA19 PA20 PA21 PA22_CK PA28_CMD
pad class "PAD with VIA": U2-33 U13-9 U14-9 U15-37 U19-57 U21-65 U24-65 U31-17 U32-37
differential pair TR3: +TR3_P -TR3_N
differential pair TR2: +TR2_P -TR2_N
differential pair TR1: +TR1_P -TR1_N
differential pair TR0: +TR0_P -TR0_N
differential pair SENSE4: +SENSE4_P -SENSE4_N
differential pair SENSE3: +SENSE3_P -SENSE3_N
differential pair SENSE2: +SENSE2_P -SENSE2_N
differential pair SENSE1: +SENSE1_P -SENSE1_N
differential pair rxb: +rxb_p -rxb_n
differential pair rxa: +rxa_p -rxa_n
differential pair USBD1: +USBD1_p -USBD1_n
differential pair USBD2: +USBD2_p -USBD2_n
differential pair USBD3: +USBD3_p -USBD3_n
differential pair USBD4: +USBD4_p -USBD4_n
differential pair HHSA: +HHSA_p -HHSA_n
differential pair HHSB: +HHSB_p -HHSB_n
differential pair USBD_JLINK: +USBD_JLINK_P -USBD_JLINK_N
differential pair DDR_CLK: +DDR_CLK_P -DDR_CLK_N
differential pair DDR_DQS0: +DDR_DQS0_P -DDR_DQS0_N
differential pair DDR_DQS1: +DDR_DQS1_P -DDR_DQS1_N
differential pair DDR_DQS2: +DDR_DQS2_P -DDR_DQS2_N
differential pair DDR_DQS3: +DDR_DQS3_P -DDR_DQS3_N
differential pair RX1: +RX1_P -RX1_N
differential pair RX2: +RX2_P -RX2_N
differential pair TX1: +TX1_P -TX1_N
differential pair TX2: +TX2_P -TX2_N
differential pair rxa1: +rxa1_p -rxa1_n
differential pair rxb1: +rxb1_p -rxb1_n
differential pair txa1: +txa1_p -txa1_n
differential pair txb1: +txb1_p -txb1_n
differential pair txa: +txa_p -txa_n
differential pair txb: +txb_p -txb_n

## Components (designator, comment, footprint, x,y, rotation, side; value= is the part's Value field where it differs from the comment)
C1 "Capacitor NP" CAP_C_0603 14.3,89.5 r270 bottom value=1uF
C2 "Capacitor NP" CAP_C_0402 32.3,81.7 r180 top value=0.1uF
C3 "Capacitor NP" CAP_C_0402 24.5,79.7 r270 bottom value=2.2uF
C4 "Capacitor NP" CAP_C_0402 15.3,91.8 r0 bottom value=0.1uF
C5 "Capacitor POL" CAP_SMD_ECH-U1C471JX5 44.3,47.9 r180 top value=220mF
C6 "Capacitor NP" CAP_C_0402 20.7,90.25 r90 bottom value=0.1uF
C7 "Capacitor NP" CAP_C_0402 40.4,42.8 r270 bottom value=0.1uF
C8 "Capacitor NP" CAP_C_0402 32.3,79.5 r180 top value=2.2uF
C9 "Capacitor NP" CAP_C_0402 32.3,78.4 r180 top value=2.2uF
C10 "Capacitor NP" CAP_C_0402 32.3,80.6 r180 top value=2.2uF
C11 "Capacitor NP" CAP_C_0402 25.4,75 r180 bottom value=4.7uF
C12 "Capacitor NP" CAP_C_0805 24.2,70.2 r180 top value=22uF
C13 "Capacitor NP" CAP_C_0402 28.6,75 r0 bottom value=4.7uF
C14 "Capacitor NP" CAP_C_0805 32.3,73.9 r270 top value=22uF
C15 "Capacitor NP" CAP_C_0402 28.6,83.05 r0 bottom value=4.7uF
C16 "Capacitor NP" CAP_C_0805 32.3,83.9 r90 top value=22uF
C17 "Capacitor NP" CAP_C_0402 25.4,83.05 r180 bottom value=4.7uF
C18 "Capacitor NP" CAP_C_0805 21.7,85.1 r90 top value=22uF
C19 "Capacitor NP" CAP_C_0402 23,91.5 r0 bottom value=0.1uF
C20 "Capacitor NP" CAP_C_0402 40.3,68.9 r180 bottom value=2.2uF
C21 "Capacitor NP" CAP_C_0402 40.3,68.9 r180 top value=0.1uF
C22 "Capacitor NP" CAP_C_0402 36,72.9 r0 top value=2.2uF
C23 "Capacitor NP" CAP_C_0402 82.7,56.9 r180 bottom value=4.7uF
C24 "Capacitor NP" CAP_C_0402 36,72.9 r0 bottom value=0.1uF
C25 "Capacitor NP" CAP_C_0402 80.85,55.7 r180 bottom value=0.1uF
C26 "Capacitor NP" CAP_C_0402 83.75,53.7 r180 bottom value=0.1uF
C27 "Capacitor NP" CAP_C_0201 70.65,55.1 r270 bottom value=22pF
C28 "Capacitor NP" CAP_C_0402 71.2,53 r180 bottom value=0.1uF
C29 "Capacitor NP" CAP_C_0805 42.5,76.4 r270 bottom value=10uF
C30 "Capacitor NP" CAP_C_0805 75.2,65.5 r0 bottom value=10uF
C31 "Capacitor NP" CAP_C_0201 60,48.8 r270 bottom value=0.1uF
C32 "Capacitor NP" CAP_C_0805 58,58.1 r0 bottom value=10uF
C33 "Capacitor NP" CAP_C_0201 69.2,48.4 r0 bottom value=0.1uF
C34 "Capacitor NP" CAP_C_0201 58.8,48.4 r0 bottom value=0.1uF
C35 "Capacitor NP" CAP_C_0201 64,47.2 r270 bottom value=0.1uF
C36 "Capacitor NP" CAP_C_0201 65.6,54.4 r90 bottom value=0.1uF
C37 "Capacitor NP" CAP_C_0201 62.4,52.8 r90 bottom value=0.1uF
C38 "Capacitor NP" CAP_C_0201 64,52 r90 bottom value=0.1uF
C39 "Capacitor NP" CAP_C_0201 60,47.2 r270 bottom value=0.1uF
C40 "Capacitor NP" CAP_C_0201 66.4,54.4 r90 bottom value=0.1uF
C41 "Capacitor NP" CAP_C_0201 61.6,53.6 r90 bottom value=0.1uF
C42 "Capacitor NP" CAP_C_0201 64,53.6 r90 bottom value=0.1uF
C43 "Capacitor NP" CAP_C_0201 69.2,49.2 r0 bottom value=0.1uF
C44 "Capacitor NP" CAP_C_0201 66.8,50 r0 bottom value=0.1uF
C45 "Capacitor NP" CAP_C_0201 69.2,50 r0 bottom value=0.1uF
C46 "Capacitor NP" CAP_C_0201 68.8,45.6 r270 bottom value=0.1uF
C47 "Capacitor NP" CAP_C_0201 65.2,44.4 r180 bottom value=0.1uF
C48 "Capacitor NP" CAP_C_0201 62.4,54.4 r90 bottom value=0.1uF
C49 "Capacitor NP" CAP_C_0201 69.2,54.8 r0 bottom value=0.1uF
C50 "Capacitor NP" CAP_C_0201 68,45.6 r90 bottom value=0.1uF
C51 "Capacitor NP" CAP_C_0402 53.65,45.05 r90 top value=18pF
C52 "Capacitor NP" CAP_C_0402 64.1,36.9 r270 top value=0.1uF
C53 "Capacitor NP" CAP_C_0201 58.8,50.8 r180 bottom value=0.1uF
C54 "Capacitor NP" CAP_C_0201 69.2,53.2 r0 bottom value=0.1uF
C55 "Capacitor NP" CAP_C_0201 67.6,48.4 r180 bottom value=0.1uF
C56 "Capacitor NP" CAP_C_0201 63.2,47.2 r270 bottom value=0.1uF
C57 "Capacitor NP" CAP_C_0402 59.1,42.6 r180 bottom value=4.7uF
C58 "Capacitor NP" CAP_C_0402 94.55,41.45 r270 bottom value=0.1uF
C59 "Capacitor NP" CAP_C_0402 93.9,38.3 r0 bottom value=0.1uF
C60 "Capacitor NP" CAP_C_0402 62.6,39.5 r180 top value=18pF
C61 "Capacitor NP" CAP_C_0201 58.8,43.6 r180 bottom value=0.1uF
C62 "Capacitor NP" CAP_C_0402 54,37.7 r90 bottom value=4.7uF
C63 "Capacitor NP" CAP_C_0402 66,42.3 r180 bottom value=22pF
C64 "Capacitor NP" CAP_C_0201 62.4,46.4 r270 bottom value=0.1uF
C65 "Capacitor NP" CAP_C_0201 61.6,46.4 r270 bottom value=0.1uF
C66 "Capacitor NP" CAP_C_0201 65.6,45.6 r90 bottom value=0.1uF
C67 "Capacitor NP" CAP_C_0402 60.5,39.5 r0 top value=18pF
C68 "Capacitor NP" CAP_C_0402 52.2,49.3 r270 bottom value=0.1uF
C69 "Capacitor NP" CAP_C_0402 58.6,41.6 r0 top value=4.7uF
C70 "Capacitor NP" CAP_C_0201 60,44 r270 bottom value=0.1uF
C71 "Capacitor NP" CAP_C_0402 60.8,41.1 r90 bottom value=4.7uF
C72 "Capacitor NP" CAP_C_0201 61.2,43.6 r0 bottom value=0.1uF
C73 "Capacitor NP" CAP_C_0201 59.6,52.4 r0 bottom value=0.1uF
C74 "Capacitor NP" CAP_C_0201 64,45.6 r270 bottom value=10pF
C75 "Capacitor NP" CAP_C_0402 93,65.8 r180 bottom value=2.2uF
C76 "Capacitor NP" CAP_C_0402 82.6,67.4 r0 top value=0.1uF
C77 "Capacitor NP" CAP_C_0402 84.6,67.4 r180 top value=0.1uF
C78 "Capacitor NP" CAP_C_0402 104.9,30.8 r180 top value=0.1uF
C79 "Capacitor NP" CAP_C_0402 86.6,67.4 r0 top value=0.1uF
C80 "Capacitor NP" CAP_C_0402 91.2,67.4 r180 top value=0.1uF
C81 "Capacitor NP" CAP_C_0402 93.2,67.4 r180 top value=0.1uF
C82 "Capacitor NP" CAP_C_0402 80,65.5 r270 top value=0.1uF
C83 "Capacitor NP" CAP_C_0402 84.2,65.3 r90 bottom value=0.1uF
C84 "Capacitor NP" CAP_C_0402 85.8,65.1 r270 bottom value=0.1uF
C85 "Capacitor NP" CAP_C_0402 106,37.2 r270 top value=0.1uF
C86 "Capacitor NP" CAP_C_0402 88.2,66.1 r0 bottom value=0.1uF
C87 "Capacitor NP" CAP_C_0402 83.8,58.4 r180 bottom value=2.2uF
C88 "Capacitor NP" CAP_C_0402 82.2,61.3 r0 bottom value=0.1uF
C89 "Capacitor NP" CAP_C_0402 84.2,60.1 r90 bottom value=0.1uF
C90 "Capacitor NP" CAP_C_0402 85.8,60.3 r90 bottom value=0.1uF
C91 "Capacitor NP" CAP_C_0402 88.237,59.6 r90 bottom value=0.1uF
C92 "Capacitor NP" CAP_C_0402 48.2,66.9 r90 top value=0.1uF
C93 "Capacitor NP" CAP_C_0402 81.7,58 r180 top value=0.1uF
C94 "Capacitor NP" CAP_C_0402 83.6,58 r180 top value=0.1uF
C95 "Capacitor NP" CAP_C_0402 85.5,58 r180 top value=0.1uF
C96 "Capacitor NP" CAP_C_0402 91.4,57.9 r180 top value=0.1uF
C97 "Capacitor NP" CAP_C_0402 93.4,58 r180 top value=0.1uF
C98 "Capacitor NP" CAP_C_0402 48.2,57.6 r90 top value=0.1uF
C99 "Capacitor NP" CAP_C_0402 82.5,49.063 r0 bottom value=2.2uF
C100 "Capacitor NP" CAP_C_0402 92.9,40.4 r180 bottom value=2.2uF
C101 "Capacitor NP" CAP_C_0402 82.5,49.4 r0 top value=0.1uF
C102 "Capacitor NP" CAP_C_0402 84.5,49.4 r180 top value=0.1uF
C103 "Capacitor NP" CAP_C_0402 86.5,49.4 r0 top value=0.1uF
C104 "Capacitor NP" CAP_C_0402 91.3,49.5 r180 top value=0.1uF
C105 "Capacitor NP" CAP_C_0402 93.2,49.4 r180 top value=0.1uF
C106 "Capacitor NP" CAP_C_0402 79.9,47.5 r270 top value=0.1uF
C107 "Capacitor NP" CAP_C_0402 83.7,47.5 r0 bottom value=0.1uF
C108 "Capacitor NP" CAP_C_0402 85.7,46.3 r270 bottom value=0.1uF
C109 "Capacitor NP" CAP_C_0402 48.2,62.4 r90 top value=0.1uF
C110 "Capacitor NP" CAP_C_0402 88.175,47.8 r270 bottom value=0.1uF
C111 "Capacitor NP" CAP_C_0402 82.1,43.5 r0 bottom value=0.1uF
C112 "Capacitor NP" CAP_C_0402 83.7,41.9 r0 bottom value=0.1uF
C113 "Capacitor NP" CAP_C_0402 86,41.9 r0 bottom value=0.1uF
C114 "Capacitor NP" CAP_C_0402 89.5,41 r90 bottom value=0.1uF
C115 "Capacitor NP" CAP_C_0402 81.7,40 r180 top value=0.1uF
C116 "Capacitor NP" CAP_C_0805 109.4,24.9 r90 top value=10uF
C117 "Capacitor NP" CAP_C_0402 83.7,40 r180 top value=0.1uF
C118 "Capacitor NP" CAP_C_0402 85.6,40 r180 top value=0.1uF
C119 "Capacitor NP" CAP_C_0402 107.8,25.5 r90 top value=0.1uF
C120 "Capacitor NP" CAP_C_0402 91.3,40 r180 top value=0.1uF
C121 "Capacitor NP" CAP_C_0402 93.2,40 r180 top value=0.1uF
C122 "Capacitor NP" CAP_C_0402 44.73,21.8 r90 top value=0.1uF
C123 "Capacitor NP" CAP_C_0402 44.445,28.245 r90 top value=0.1uF
C124 "Capacitor NP" CAP_C_0603 48.231,73.069 r270 top value=15pF
C125 "Capacitor NP" CAP_C_0603 55.831,72.794 r270 top value=15pF
C126 "Capacitor NP" CAP_C_0402 52.18,21.675 r180 bottom value=0.1uF
C127 "Capacitor NP" CAP_C_0402 55.9,27.1 r90 bottom value=0.1uF
C128 "Capacitor NP" CAP_C_0402 52.1,25.3 r180 bottom value=0.1uF
C129 "Capacitor NP" CAP_C_0402 48.231,75.569 r90 top value=0.1uF
C130 "Capacitor NP" CAP_C_0402 55.7,75.3 r90 top value=0.1uF
C131 "Capacitor NP" CAP_C_0402 46.025,74.369 r270 bottom value=0.1uF
C132 "Capacitor NP" CAP_C_0402 53.525,74.369 r270 bottom value=0.1uF
C133 "Capacitor NP" CAP_C_0402 57.6,24.3 r0 bottom value=0.1uF
C134 "Capacitor NP" CAP_C_0402 55.9,21.5 r270 bottom value=0.1uF
C135 "Capacitor NP" CAP_C_0402 57.6,23.2 r0 bottom value=0.1uF
C136 "Capacitor NP" CAP_C_0603 38.2,92.2 r180 bottom value=100pF
C137 "Capacitor NP" CAP_C_0603 45.5,92.2 r0 bottom value=100pF
C138 "Capacitor NP" CAP_C_0603 50.2,92.2 r180 bottom value=100pF
C139 "Capacitor NP" CAP_C_0603 56.4,92.2 r0 bottom value=100pF
C140 "Capacitor NP" CAP_C_0603 41.9,94 r180 bottom value=100pF
C141 "Capacitor NP" CAP_C_0603 53.3,94 r180 bottom value=100pF
C142 "Capacitor NP" CAP_C_0805 41.9,89.4 r270 bottom value=4700pF
C143 "Capacitor NP" CAP_C_0805 53.3,89.5 r270 bottom value=4700pF
C144 "Capacitor NP" CAP_C_0402 41.05,1 r180 bottom value=0.1uF
C145 "Capacitor NP" CAP_C_0402 60.6,1 r180 bottom value=0.1uF
C146 "Capacitor NP" CAP_C_0603 58.3,26.4 r270 bottom value=1uF
C147 "Capacitor NP" CAP_C_0603 46,9.3 r270 bottom value=22uF
C148 "Capacitor NP" CAP_C_0402 42.1,10 r180 bottom value=0.1uF
C149 "Capacitor NP" CAP_C_0402 61.24,9.99 r180 bottom value=0.1uF
C150 "Capacitor NP" CAP_C_0603 65.14,9.29 r270 bottom value=22uF
C151 "Capacitor NP" CAP_C_0603 44.5,9.3 r270 bottom value=22uF
C152 "Capacitor NP" CAP_C_0402 75.802,2.374 r90 top value=22pF
C153 "Capacitor NP" CAP_C_0402 48.4,10 r0 bottom value=0.1uF
C154 "Capacitor NP" CAP_C_0402 67.55,9.9 r0 bottom value=0.1uF
C155 "Capacitor NP" CAP_C_0402 35.5,42.255 r270 top value=0.1uF
C156 "Capacitor NP" CAP_C_0402 34.3,40.1 r90 bottom value=0.1uF
C157 "Capacitor NP" CAP_C_0603 24.2,41.655 r270 bottom value=1uF
C158 "Capacitor NP" CAP_C_0603 26.3,39.7 r90 bottom value=1uF
C159 "Capacitor NP" CAP_C_0603 24.2,41.655 r270 top value=1uF
C160 "Capacitor NP" CAP_C_0603 28.1,24 r90 top value=22uF
C161 "Capacitor NP" CAP_C_0402 31.5,39.25 r90 bottom value=10nF
C162 "Capacitor NP" CAP_C_0402 125.9,55.5 r90 bottom value=10pF
C163 "Capacitor NP" CAP_C_0805 27.8,31.2 r270 bottom value=10uF
C164 "Capacitor NP" CAP_C_0402 125.9,57.5 r270 bottom value=10pF
C165 "Capacitor NP" CAP_C_0402 125.9,55.5 r90 top value=10pF
C166 "Capacitor NP" CAP_C_0402 125.9,57.5 r270 top value=10pF
C167 "Capacitor NP" CAP_C_0402 31.5,21.5 r180 top value=0.1uF
C168 "Capacitor NP" CAP_C_0402 24.8,37.6 r180 bottom value=10nF
C169 "Capacitor NP" CAP_C_0402 32.8,39.2 r90 bottom value=10nF
C170 "Capacitor NP" CAP_C_0402 24.8,36.4 r180 bottom value=10nF
C171 "Capacitor NP" CAP_C_0402 30.3,39.25 r90 bottom value=10nF
C172 "Capacitor NP" CAP_C_0402 24.8,34.9 r180 bottom value=10nF
C173 "Capacitor NP" CAP_C_0402 30.4,31.95 r270 bottom value=10nF
C174 "Capacitor NP" CAP_C_0402 32.05,34.975 r0 bottom value=10nF
C175 "Capacitor NP" CAP_C_0402 24.8,33.7 r180 bottom value=10nF
C176 "Capacitor NP" CAP_C_0402 24.8,32.555 r180 bottom value=10nF
C177 "Capacitor NP" CAP_C_0402 27.9,39.2 r90 bottom value=10nF
C178 "Capacitor NP" CAP_C_0402 32.05,33.85 r0 bottom value=10nF
C179 "Capacitor NP" CAP_C_0402 29.1,39.25 r90 bottom value=10nF
C180 "Capacitor NP" CAP_C_0402 31.5,32 r270 bottom value=10nF
C181 "Capacitor NP" CAP_C_0603 119.9,60.2 r270 bottom value=0.022uF
C182 "Capacitor NP" CAP_C_0402 23.1,67.2 r90 top value=0.1uF
C183 "Capacitor NP" CAP_C_0402 29.3,64.5 r0 top value=22pF
C184 "Capacitor NP" CAP_C_0402 38.1,63.4 r180 bottom value=0.1uF
C185 "Capacitor NP" CAP_C_0603 23.9,62.3 r270 bottom value=22uF
C186 "Capacitor NP" CAP_C_0603 34.1,62.6 r0 bottom value=22uF
C187 "Capacitor NP" CAP_C_0603 25.4,62.3 r270 bottom value=22uF
C188 "Capacitor NP" CAP_C_0603 34.1,64 r0 bottom value=22uF
C189 "Capacitor NP" CAP_C_0402 31.3,64.5 r180 top value=22pF
C190 "Capacitor NP" CAP_C_0402 24.2,59.8 r0 bottom value=0.1uF
C191 "Capacitor NP" CAP_C_0402 34.4,66.5 r0 bottom value=0.1uF
C192 "Capacitor NP" CAP_C_0402 24.2,59.8 r0 top value=0.1uF
C193 "Capacitor NP" CAP_C_0402 34.4,65.3 r0 bottom value=0.1uF
C194 "Capacitor NP" CAP_C_0402 27.6,58.6 r180 bottom value=0.1uF
C195 "Capacitor NP" CAP_C_0402 27.6,53 r180 bottom value=0.1uF
C196 "Capacitor NP" CAP_C_0402 27.6,55.3 r180 bottom value=0.1uF
C197 "Capacitor NP" CAP_C_0402 27.6,56.4 r180 bottom value=0.1uF
C198 "Capacitor NP" CAP_C_0402 27.6,57.5 r180 bottom value=0.1uF
C199 "Capacitor NP" CAP_C_0402 27.6,59.7 r180 bottom value=0.1uF
C200 "Capacitor NP" CAP_C_0402 27.6,54.2 r180 bottom value=0.1uF
C201 "Capacitor NP" CAP_C_0402 29.7,60.4 r90 bottom value=0.1uF
C202 "Capacitor NP" CAP_C_0402 31.9,60.4 r90 bottom value=0.1uF
C203 "Capacitor NP" CAP_C_0402 29.1,52.55 r270 bottom value=0.1uF
C204 "Capacitor NP" CAP_C_0402 34.7,60 r0 bottom value=0.1uF
C205 "Capacitor NP" CAP_C_0402 33.9,52.55 r270 bottom value=0.1uF
C206 "Capacitor NP" CAP_C_0402 35.4,55.7 r0 bottom value=0.1uF
C207 "Capacitor NP" CAP_C_0402 35.4,53.7 r0 bottom value=0.1uF
C208 "Capacitor NP" CAP_C_0402 35.4,54.7 r0 bottom value=0.1uF
C209 "Capacitor NP" CAP_C_0402 35.4,57.1 r0 bottom value=0.1uF
C210 "Capacitor NP" CAP_C_0402 30.9,52.6 r270 bottom value=0.1uF
C211 "Capacitor NP" CAP_C_0402 33,60.4 r90 bottom value=0.1uF
C212 "Capacitor NP" CAP_C_0402 30.8,60.4 r90 bottom value=0.1uF
C213 "Capacitor NP" CAP_C_0402 15,75.3 r180 bottom value=0.1uF
C214 "Capacitor NP" CAP_C_0402 15,74 r180 bottom value=0.1uF
C215 "Capacitor NP" CAP_C_0402 15,56.2 r180 bottom value=0.1uF
C216 "Capacitor NP" CAP_C_0402 15,55 r180 bottom value=0.1uF
C217 "Capacitor NP" CAP_C_0402 109,56.7 r180 bottom value=0.1uF
C218 "Capacitor NP" CAP_C_0402 109.6,63.4 r180 top value=0.1uF
C219 "Capacitor NP" CAP_C_0402 112.4,53.1 r90 bottom value=0.1uF
C220 "Capacitor NP" CAP_C_0402 107.8,46.4 r180 bottom value=0.1uF
C221 "Capacitor NP" CAP_C_0402 103.5,43.1 r0 top value=0.1uF
C222 "Capacitor NP" CAP_C_0402 113.2,59.9 r90 top value=22pF
C223 "Capacitor NP" CAP_C_0402 108.8,53.4 r90 bottom value=0.1uF
C224 "Capacitor NP" CAP_C_0402 114.7,62.4 r0 top value=0.1uF
C225 "Capacitor NP" CAP_C_0402 114.8,53.3 r90 bottom value=0.1uF
C226 "Capacitor NP" CAP_C_0603 115.45,56.1 r0 bottom value=1uF
C227 "Capacitor NP" CAP_C_0603 115.5,44.2 r0 bottom value=1uF
C228 "Capacitor NP" CAP_C_0402 115.45,42.8 r180 top value=0.1uF
C229 "Capacitor NP" CAP_C_0402 112.4,55.9 r90 top value=22pF
C230 "Capacitor NP" CAP_C_0402 107.8,51.6 r180 bottom value=0.1uF
C231 "Capacitor NP" CAP_C_0402 115.8,54.825 r0 bottom value=0.1uF
C232 "Capacitor NP" CAP_C_0402 115.8,45.5 r0 bottom value=0.1uF
C233 "Capacitor NP" CAP_C_0402 116,53.3 r90 bottom value=0.1uF
C234 "Capacitor NP" CAP_C_0402 115.8,46.75 r0 bottom value=0.1uF
C235 "Capacitor NP" CAP_C_0402 117.4,39.8 r90 bottom value=0.1uF
C236 "Capacitor NP" CAP_C_0603 125,50 r180 bottom value=1uF
C237 "Capacitor NP" CAP_C_0402 111.2,45.6 r270 bottom value=0.1uF
C238 "Capacitor NP" CAP_C_0402 107.8,48.9 r180 bottom value=0.1uF
C239 "Capacitor NP" CAP_C_0402 113.7,53.3 r90 bottom value=0.1uF
C240 "Capacitor NP" CAP_C_0402 125.9,46.2 r270 bottom value=10pF
C241 "Capacitor NP" CAP_C_0402 48.8,80.5 r180 bottom value=0.1uF
C242 "Capacitor NP" CAP_C_0402 125.9,44.3 r90 bottom value=10pF
C244 "Capacitor NP" CAP_C_0402 125.9,46.2 r270 top value=10pF
C245 "Capacitor NP" CAP_C_0402 22.779,41.355 r270 bottom value=10nF
C246 "Capacitor NP" CAP_C_0402 125.9,44.3 r90 top value=10pF
C247 "Capacitor NP" CAP_C_0402 25.1,39.2 r90 bottom value=10nF
C248 "Capacitor NP" CAP_C_0603 119.7,41.4 r270 bottom value=0.022uF
C249 "Capacitor NP" CAP_C_0402 27.7,25.4 r0 bottom value=10nF
C250 "Capacitor NP" CAP_C_0402 26,15.55 r0 top value=0.1uF
C251 "Capacitor NP" CAP_C_0402 20.5,10.2 r90 top value=10000pF
C252 "Capacitor NP" CAP_C_0603 13.9,24.85 r0 bottom value=2.2uF
C253 "Capacitor NP" CAP_C_0603 19.9,24.9 r90 bottom value=2.2uF
C254 "Capacitor NP" CAP_C_0402 10.9,12.7 r0 bottom value=10000pF
C255 "Capacitor NP" CAP_C_0402 21.125,14.425 r180 top value=10pF
C256 "Capacitor NP" CAP_C_0402 18.5,24.7 r90 bottom value=0.1uF
C257 "Capacitor NP" CAP_C_0402 18.525,16.8 r180 bottom value=0.1uF
C258 "Capacitor NP" CAP_C_0603 13.5,12.5 r180 bottom value=4.7uF
C259 "Capacitor NP" CAP_C_0402 15.8,16 r180 bottom value=0.1uF
C260 "Capacitor NP" CAP_C_0402 15.9,13.25 r90 bottom value=0.1uF
C261 "Capacitor NP" CAP_C_0402 17.5,11.7 r90 bottom value=0.1uF
C262 "Capacitor NP" CAP_C_0402 18.7,11.7 r90 bottom value=0.1uF
C263 "Capacitor NP" CAP_C_0603 14.6,11.1 r180 bottom value=4.7uF
C264 "Capacitor NP" CAP_C_0402 14.7,17.5 r0 bottom value=0.1uF
C265 "Capacitor NP" CAP_C_0402 9.5,14.2 r0 bottom value=0.1uF
C266 "Capacitor NP" CAP_C_0402 17.4,15.2 r90 bottom value=0.1uF
C267 "Capacitor NP" CAP_C_0402 11.7,11 r0 bottom value=0.1uF
C268 "Capacitor NP" CAP_C_0402 13.75,16 r180 bottom value=0.1uF
C269 "Capacitor NP" CAP_C_0402 14.2,14.4 r90 bottom value=0.1uF
C270 "Capacitor NP" CAP_C_0402 11.5,16.55 r0 bottom value=0.1uF
C271 "Capacitor NP" CAP_C_0402 17.4,20.7 r0 bottom value=0.1uF
C272 "Capacitor NP" CAP_C_0402 19.55,18 r180 bottom value=0.1uF
C273 "Capacitor NP" CAP_C_0402 11.6,22.7 r0 bottom value=0.1uF
C274 "Capacitor NP" CAP_C_0402 43,54.7 r180 top value=0.1uF
C275 "Capacitor NP" CAP_C_0402 45.4,54.7 r0 bottom value=0.1uF
C276 "Capacitor NP" CAP_C_0402 20.5,22.25 r0 top value=0.1uF
C277 "Capacitor NP" CAP_C_0402 126.9,10.125 r180 top value=0.1uF
C278 "Capacitor NP" CAP_C_0402 125.2,20.965 r90 top value=0.1uF
C279 "Capacitor NP" CAP_C_1206 123.3,21.15 r90 top value=47uF
C280 "Capacitor NP" CAP_C_0402 26.3,32 r270 bottom value=10nF
C281 "Capacitor NP" CAP_C_0603 63.64,9.29 r270 bottom value=22uF
C282 "Capacitor NP" CAP_C_1210 40.8,5.5 r90 bottom value=100uF
C283 "Capacitor NP" CAP_C_1210 60,5.5 r90 bottom value=100uF
C284 "Capacitor NP" CAP_C_1206 38,5.5 r90 bottom value=47uF
C285 "Capacitor NP" CAP_C_1206 57.2,5.5 r90 bottom value=47uF
C286 "Capacitor NP" CAP_C_0603 116,50 r0 bottom value=1uF
C287 "Capacitor NP" CAP_C_0402 115.6,51.3 r0 bottom value=0.1uF
C288 "Capacitor NP" CAP_C_0402 118.7,50.75 r180 bottom value=0.1uF
C289 "Capacitor NP" CAP_C_0402 118.7,49.25 r180 bottom value=0.1uF
C290 "Capacitor POL" CAP_AL_D8 40.2,87 r90 top value=220uF
C291 "Capacitor NP" CAP_C_0402 89.775,47.8 r270 bottom value=0.1uF
C292 "Capacitor NP" CAP_C_0402 88,41 r180 bottom value=0.1uF
C293 "Capacitor NP" CAP_C_0402 90.5,65.3 r270 bottom value=0.1uF
C294 "Capacitor NP" CAP_C_0402 87.4,57.9 r180 top value=0.1uF
C295 "Capacitor NP" CAP_C_1210 49.7,5.5 r90 bottom value=100uF
C296 "Capacitor NP" CAP_C_1210 68.8,5.5 r90 bottom value=100uF
C297 "Capacitor NP" CAP_C_1206 52.5,5.5 r90 bottom value=47uF
C298 "Capacitor NP" CAP_C_1206 71.6,5.5 r90 bottom value=47uF
C299 "Capacitor NP" CAP_C_0402 53.65,47.15 r270 top value=18pF
C300 "Capacitor NP" CAP_C_1206 120.902,21.15 r90 top value=47uF
C301 "Capacitor NP" CAP_C_0402 129.6,28.5 r180 top value=0.1uF
C302 "Capacitor NP" CAP_C_0603 129.185,29.8 r0 top value=2.2uF
C303 "Capacitor NP" CAP_C_0603 119.7,14.95 r180 top value=2.2uF
C304 "Capacitor NP" CAP_C_0402 123,17.3 r90 bottom value=1000pF
C305 "Capacitor NP" CAP_C_0603 120.5,17.15 r90 top value=2.2uF
D1 "Diode Schottky" SOD-123FL 42.1,47.1 r0 bottom value=RB160M-60TR
D2 "Diode Schottky Dual CK" SOT-23-3 42.9,43.5 r0 bottom value=BAT54C
D3 "LED_red" LED_0402_RED 16.9,87 r270 top value=RED
D4 "LED_red" LED_0402_RED 44.95,24.5 r180 top value=RED
D9 "LED_green" LED_0603_GREEN 115,41.1 r180 top value=GREEN
D10 "Diode Schottky" SOD-123 22.375,8.575 r270 top value=PMEG6010ER
D11 "Diode Schottky" SOD-323 123.5,47.8 r180 bottom value=B0520WS
D12 "Diode Schottky" SOD-323 123.5,42.7 r180 bottom value=B0520WS
D13 "Diode Schottky" SOD-323 123.5,47.8 r180 top value=B0520WS
D14 "Diode Schottky" SOD-323 123.5,42.7 r180 top value=B0520WS
D15 "Diode Schottky" SOD-323 123.5,53.9 r180 bottom value=B0520WS
D16 "Diode Schottky" SOD-323 123.5,59.1 r180 bottom value=B0520WS
D17 "Diode Schottky" SOD-323 123.5,53.9 r180 top value=B0520WS
D18 "Diode Schottky" SOD-323 123.5,59.1 r180 top value=B0520WS
D19 "Diode TVS Bidirectional" DIO_C_0402 121.6,45.2 r270 bottom value=GG040205170N2P
D20 "Diode TVS Bidirectional" DIO_C_0402 121.6,45.2 r90 top value=GG040205170N2P
D21 "Diode TVS Bidirectional" DIO_C_0402 121.7,56.5 r90 bottom value=GG040205170N2P
D22 "Diode TVS Bidirectional" DIO_C_0402 121.7,56.5 r90 top value=GG040205170N2P
FB1 "Ferrite Bead" IND_C_0603 55.2,37.3 r90 bottom value=180R
FB2 "Ferrite Bead" IND_C_0603 65.7,38.23 r90 bottom value=180R
FB3 "Ferrite Bead" IND_C_0603 59.7,61.1 r0 bottom value=180R
FB4 "Ferrite Bead" IND_C_0603 59.7,62.5 r0 bottom value=180R
FB5 "Ferrite Bead" IND_C_0603 59.7,59.7 r0 bottom value=180R
FB6 "Ferrite Bead" IND_C_0603 54.9,55.2 r270 bottom value=180R
FB7 "Ferrite Bead" IND_C_0603 56.7,37.9 r90 bottom value=180R
FB8 "Ferrite Bead" IND_C_0603 54.3,49 r0 bottom value=180R
FB9 "Ferrite Bead" IND_C_0603 68.5,38 r90 bottom value=180R
FB10 "Ferrite Bead" IND_C_0603 48.2,8.6 r0 bottom value=180R
FB11 "Ferrite Bead" IND_C_0603 42.3,8.6 r180 bottom value=180R
FB12 "Ferrite Bead" IND_C_0603 67.3,8.6 r0 bottom value=180R
FB13 "Ferrite Bead" IND_C_0603 61.4,8.6 r180 bottom value=180R
FB14 "Ferrite Bead" IND_C_0603 70.223,13.143 r0 bottom value=180R
FB17 "Ferrite Bead" IND_C_0603 23.9,62.3 r270 top value=220R
FB18 "Ferrite Bead" IND_C_0603 31,25 r0 bottom value=180R
FB19 "Ferrite Bead" IND_C_0603 25.4,62.3 r270 top value=220R
FB20 "Ferrite Bead" IND_C_0603 31,26.4 r0 bottom value=180R
FB21 "Ferrite Bead" IND_C_0603 12.7,36.6 r0 bottom value=180R
FB22 "Ferrite Bead" IND_C_0603 121.7,50 r180 top value=220R
FB23 "Ferrite Bead" IND_C_0603 115.45,57.525 r0 bottom value=220R
FB24 "Ferrite Bead" IND_C_0603 115.5,42.7 r0 bottom value=220R
FB25 "Ferrite Bead" IND_C_0603 121.7,50 r180 bottom value=220R
FB26 "Ferrite Bead" IND_C_0603 5.3,5.9 r0 bottom value=180R
FB27 "Ferrite Bead" IND_C_0603 118.9,18.75 r90 top value=180R
J1 "CON JACK 2C 3P SPST" CON_JACK_POWER_TH_RA_MPD_EJ508A 11,89.2 r270 top locked value=2.1mm
J2 "Header 1x2" HDR_M_2.54_1x2 44.2,39.6 r180 top value="HDR-2.54 Male 1x2"
J3 "Header 1x2" HDR_M_2.54_1x2 1.7,90.343 r270 top value="HDR-2.54 Male 1x2"
J4 "Header 1x3" HDR_M_1.27_1x3 123.1,30.47 r270 top value="HDR-1.27 Male 1x3"
J5 "CON SD CARD 11P_amphenol" 10067847-001RLF 102.975,17.625 r180 bottom locked value=SD
J6 "CON TERM BLK 1x5 TH Mount" CON_TERMINAL_3.81_1x5_TH_RA_PHO_1727049 47.559,96.431 r0 top value="TERMINAL 1x5"
J7 "CON USB2.0 A DUAL" CON_USB2.0-A_Dual_RCPT_TH_RA_AMN_AU-Y1008-2 45.26,13.14 r0 top locked value="USB2.0 STD-A DUAL FEMALE"
J8 "CON USB2.0 A DUAL" CON_USB2.0-A_Dual_RCPT_TH_RA_AMN_AU-Y1008-2 64.4,13.14 r0 top locked value="USB2.0 STD-A DUAL FEMALE"
J9 "CON USB2.0 Mini_Micro" CON_USB_Micro-AB_SMD_RA_MOLEX_0475890001 81.7,2.1 r0 top value=0475890001
J10 "CON_RJ-45_TH_RA_PULSE_JD1-0001NL" CON_RJ-45_TH_RA_PULSE_JD1-0001NL 10.9,36.615 r270 top value="CON MODULAR JACK RJ45 10/100/1000 MAGNETICS 2xLEDs SHIELD TH R/A"
J11 "RJ45 J00-0045NL" J00-0045NL_RJ45_CONNECTOR 10.9,74.6 r270 top locked value=RJ45
J12 "RJ45 J00-0045NL" J00-0045NL_RJ45_CONNECTOR 10.9,55.6 r270 top locked value=RJ45
J13 "RJ45 J00-0045NL" J00-0045NL_RJ45_CONNECTOR 139.1,42.015 r90 top value=RJ45
J14 "RJ45 J00-0045NL" J00-0045NL_RJ45_CONNECTOR 139.1,60.885 r90 top value=RJ45
J15 "pads on PCB" CON_EDGE-CARD_PCB_RA_MEC1-108-02-F-D-RA1-SL 17.825,3.625 r0 top locked
J16 "CON USB2.0 Mini_Micro" CON_USB_Micro-AB_SMD_RA_MOLEX_0475890001 2.1,10.1 r270 top value=0475890001
J17 "Header 1x2" HDR_M_2.54_1x2 3,17 r0 top value="HDR-2.54 Male 1x2"
J18 "Header 2x5" HDR_M_1.27_2x5_SMD_V_SAM_FTSH-105-01-F-DV-K 27.75,6.6 r180 top value="HDR-1.27 Male 2x5"
J19 "Header 1x2" HDR_M_2.54_1x2 3,25 r180 top value="HDR-2.54 Male 1x2"
J20 "Header 1x2" HDR_M_2.54_1x2 3,21 r180 top value="HDR-2.54 Male 1x2"
J21 "SOCKET mikroBUS HOST" SOCKET_mikroBUS_F_2.54_2x8_V_25.4x21 73.13,84.605 r0 top locked value="mikroBUS HOST"
J22 "SOCKET mikroBUS HOST" SOCKET_mikroBUS_F_2.54_2x8_V_25.4x21 102.13,84.565 r0 top locked value="mikroBUS HOST"
J23 "SOCKET mikroBUS HOST" SOCKET_mikroBUS_F_2.54_2x8_V_25.4x21 131.15,84.575 r0 top locked value="mikroBUS HOST"
J24 "Header 2x5" HDR_M_2.54_2x5_SMD_SAM_TSM-105-01-T-DV 70,26 r90 top value="HDR-2.54 Male 2x5"
J25 "Header 1x3" HDR_M_1.27_1x3 123.1,25.63 r90 top value="HDR-1.27 Male 1x3"
J26 "Header 1x8" HDR_M_2.54_1x8 132.31,7.8 r180 top value="HDR-2.54 Male 1x8"
J27 "Header 1x3" HDR_M_2.54_1x3 43.6,62.3 r270 top value="HDR-2.54 Male 1x3"
L1 "Inductor" IND_C_1212 24.85,73.65 r180 top value=1.5uH
L2 "Inductor" IND_C_1212 29.15,73.65 r0 top value=1.5uH
L3 "Inductor" IND_C_1212 29.15,84.35 r0 top value=1.5uH
L4 "Inductor" IND_C_1212 24.85,84.35 r180 top value=1.5uH
L5 "Inductor" IND_C_0603 59.6,40.8 r90 bottom value=10uH
L6 "Inductor" IND_C_0603 62,40.8 r90 bottom value=10uH
L7 "Inductor" IND_C_0603 58.2,40.8 r90 bottom value=10uH
L8 "Inductor Choke" IND_EP_SIMDAD_1812 45.7,82.1 r0 top value=B82789S223N2
L9 "Inductor Choke" IND_EP_SIMDAD_1812 53.2,82.1 r0 top value=B82789S223N2
L10 "Inductor" IND_SRN3015TA 26.2,28.9 r0 top value=3.3uH
LABEL1 "LABEL_Need_Help_Small" LABEL_Need_Help_Small 79.55,24.25 r90 bottom value="LABEL Need Help Small"
LD1 "LED_green" LED_0603_GREEN 55.6,2.8 r270 top value=GREEN
LD2 "LED_green" LED_0603_GREEN 73.2,2.8 r270 top value=GREEN
LD3 "LED_green" LED_0603_GREEN 36.46,2.81 r270 top value=GREEN
LD4 "LED_green" LED_0603_GREEN 54.06,2.81 r270 top value=GREEN
LD5 "LED_RGB_CLV1A" PLCC-4_CLV1A-FKB 28.3,45.255 r0 top value="RED, GREEN, BLUE"
LD6 "LED DUAL 4 pin" LED_DUAL_SMD_2x1.25mm 22.65,16.575 r0 top value="RED, GREEN"
LD7 "LED_RGB_CLV1A" PLCC-4_CLV1A-FKB 87.3,29.6 r0 top value="RED, GREEN, BLUE"
LD8 "LED DUAL 4 pin" LED_DUAL_SMD_2x1.25mm 120.3,7.9 r270 top value="RED, GREEN"
Q1 "SIA923AEDJ-T1-GE3" "SiA923AEDJ PPAK_SC70_6L" 21.9,93.5 r0 bottom value=SIA923AEDJ
Q2 "SIA923AEDJ-T1-GE3" "SiA923AEDJ PPAK_SC70_6L" 18.5,93.5 r0 bottom value=SIA923AEDJ
Q3 "Transistor MOS-N GSD" SOT-23-3 87.3,35 r0 bottom value=BSS138N
Q4 "Transistor MOS-N GSD" SOT-23-3 92,32.5 r0 top value=BSS138N
Q5 "Transistor MOS-N GSD" SOT-23-3 82.6,32.5 r0 top value=BSS138N
Q6 "Transistor MOS-N GSD" SOT-23-3 38.3,66.8 r180 bottom value=BSS138N
R1 "Resistor" RES_C_0402 22.2,81.3 r180 bottom value=10k
R2 "Resistor" RES_C_0402 22.2,79.9 r180 bottom value=10k
R3 "Resistor" RES_C_0805 45.8,45.9 r270 bottom value=100R
R4 "Resistor" RES_C_0402 88.175,49.925 r0 bottom value=0R
R5 "Resistor" RES_C_0402 60.1,41.2 r90 top value=0R
R6 "Resistor" RES_C_0603 21.8,75.6 r90 bottom value=1k
R7 "Resistor" RES_C_0402 32.3,76.2 r0 top value=0R
R8 "Resistor" RES_C_0402 32.3,77.3 r180 top value=0R
R9 "Resistor" RES_C_0402 32.3,76.2 r0 bottom value=0R
R10 "Resistor" RES_C_0402 32.3,77.3 r180 bottom value=0R
R11 "Resistor" RES_C_0402 15.304,93.085 r180 bottom value=100k
R12 "Resistor" RES_C_0402 19.3,90.25 r90 bottom value=10k
R13 "Resistor" RES_C_0402 18,95.5 r180 bottom value=100k
R14 "Resistor" RES_C_0603 16.9,87 r270 bottom value=2.2k
R15 "Shunt 4 Pin" RES_C_1206_SHUNT 36.5,70 r0 top value=0.01R
R16 "Shunt 4 Pin" RES_C_1206_SHUNT 42.5,70.5 r90 top value=0.01R
R17 "Shunt 4 Pin" RES_C_1206_SHUNT 36.5,77 r0 top value=0.01R
R18 "Shunt 4 Pin" RES_C_1206_SHUNT 42.5,76.5 r270 top value=0.01R
R19 "Resistor" RES_C_0603 59.6,37.9 r90 bottom value=2.2R
R20 "Resistor" RES_C_0603 62,37.9 r90 bottom value=2.2R
R21 "Resistor" RES_C_0603 58.2,37.9 r90 bottom value=2.2R
R22 "Resistor" RES_C_0402 40,75.9 r270 top value=0R
R23 "Resistor" RES_C_0402 36,74.1 r180 top value=10k
R24 "Resistor" RES_C_0402 36,74.1 r180 bottom value=10k
R25 "Resistor" RES_C_0603 81.15,54 r180 bottom value=2.2k
R26 "Resistor" RES_C_0603 83.55,55.4 r180 bottom value=2.2k
R27 "Resistor" RES_C_0402 100.3,39.1 r0 bottom value=22R
R28 "Resistor" RES_C_0402 100.3,37.9 r0 bottom value=22R
R29 "Resistor" RES_C_0402 100.3,41.65 r0 bottom value=22R
R30 "Resistor" RES_C_0402 100.3,40.3 r0 bottom value=22R
R31 "Resistor" RES_C_0402 100.3,34.3 r0 top value=22R
R32 "Resistor" RES_C_0402 100.3,34.3 r0 bottom value=22R
R33 "Resistor" RES_C_0402 100.3,36.7 r0 top value=22R
R34 "Resistor" RES_C_0402 100.3,36.7 r0 bottom value=22R
R35 "Resistor" RES_C_0402 100.3,31.9 r0 top value=22R
R36 "Resistor" RES_C_0402 100.3,31.9 r0 bottom value=22R
R37 "Resistor" RES_C_0402 100.3,33.1 r0 top value=22R
R38 "Resistor" RES_C_0402 100.3,33.1 r0 bottom value=22R
R39 "Resistor" RES_C_0402 100.3,35.5 r0 top value=22R
R40 "Resistor" RES_C_0402 100.3,35.5 r0 bottom value=22R
R41 "Resistor" RES_C_0402 100.3,29.1 r0 top value=22R
R42 "Resistor" RES_C_0603 50.1,54.2 r0 bottom value=2.2k
R43 "Resistor" RES_C_0603 52.6,50.5 r180 top value=2.2k
R44 "Resistor" RES_C_0603 48.5,69.4 r0 bottom value=2.2k
R45 "Resistor" RES_C_0603 50.9,52.7 r180 bottom value=2.2k
R46 "Resistor" RES_C_0603 51.8,49.1 r180 top value=2.2k
R47 "Resistor" RES_C_0603 48.5,71.8 r0 bottom value=2.2k
R48 "Resistor" RES_C_0402 51.5,64.8 r180 bottom value=22R
R49 "Resistor" RES_C_0402 51.5,59.8 r180 bottom value=22R
R50 "Resistor" RES_C_0402 51.5,55.5 r180 bottom value=22R
R51 "Resistor" RES_C_0402 49.5,64.8 r0 bottom value=22R
R52 "Resistor" RES_C_0402 49.5,59.8 r0 bottom value=22R
R53 "Resistor" RES_C_0402 49.5,55.5 r0 bottom value=22R
R54 "Resistor" RES_C_0402 53.6,64.7 r0 bottom value=22R
R55 "Resistor" RES_C_0402 53.6,61.9 r0 bottom value=22R
R56 "Resistor" RES_C_0402 53.6,59.3 r0 bottom value=22R
R57 "Resistor" RES_C_0402 53.6,66.2 r0 bottom value=22R
R58 "Resistor" RES_C_0402 53.6,63.3 r0 bottom value=22R
R59 "Resistor" RES_C_0402 53.6,60.7 r0 bottom value=22R
R60 "Resistor" RES_C_0402 46,72.4 r180 bottom value=22R
R61 "Resistor" RES_C_0402 46,71.2 r180 bottom value=22R
R62 "Resistor" RES_C_0402 46,68.8 r180 bottom value=22R
R63 "Resistor" RES_C_0402 46,70 r180 bottom value=22R
R64 "Resistor" RES_C_0402 71.2,54 r180 bottom value=23.2k
R65 "Resistor" RES_C_0402 94.1,50.5 r0 top value=100k
R66 "Resistor" RES_C_0402 55.3,45.1 r180 bottom value=10k
R67 "Resistor" RES_C_0402 66,43.3 r180 bottom value=16.9k
R68 "Resistor" RES_C_0402 56.3,49.3 r90 bottom value=0R
R69 "Resistor" RES_C_0402 63.3,41.2 r90 top value=0R
R70 "Resistor" RES_C_0402 62.3,41.2 r90 top value=0R
R71 "Resistor" RES_C_0402 61.1,41.2 r90 top value=0R
R72 "Resistor" RES_C_0402 32.3,75.1 r0 bottom value=100k
R75 "Resistor" RES_C_0402 47.9,40 r90 top value=0R
R76 "Resistor" RES_C_0402 58.2,40.1 r90 top value=1R
R77 "Resistor" RES_C_0402 60.8,39.1 r90 bottom value=1R
R78 "Resistor" RES_C_0201 63.2,45.6 r270 bottom value=5.62K
R79 "Resistor" RES_C_0201 64.8,45.6 r270 bottom value=0R
R80 "Resistor" RES_C_0402 102.5,30.8 r0 top value=10k
R82 "Resistor" RES_C_0603 140,57.8 r0 bottom value=1k
R83 "Resistor" RES_C_0402 106.5,28.1 r270 top value=10k
R84 "Resistor" RES_C_0402 106,33.4 r90 top value=10k
R85 "Resistor" RES_C_0402 89.4,49.6 r180 top value=240R
R86 "Resistor" RES_C_0402 89.4,40 r180 top value=0R
R87 "Resistor" RES_C_0402 87.5,40 r0 top value=0R
R88 "Resistor" RES_C_0402 104,36.6 r90 top value=10k
R89 "Resistor" RES_C_0402 88.1,52.9 r0 bottom value=100k
R91 "Resistor" RES_C_0402 50.5,67.3 r0 bottom value=10k
R92 "Resistor" RES_C_0402 89.2,67.4 r0 top value=240R
R94 "Resistor" RES_C_0402 89.9,57.6 r90 top value=0R
R95 "Resistor" RES_C_0402 88.9,57.6 r90 top value=0R
R97 "Resistor" RES_C_0402 50.5,61 r180 bottom value=10k
R98 "Resistor" RES_C_0402 50.5,62.8 r180 bottom value=10k
R101 "Resistor Network 4-Ch" RES_C_CAV_0603x4 103.775,25.05 r270 top value=68k
R102 "Resistor" RES_C_0402 111.5,26 r180 top value=10k
R103 "Resistor" RES_C_0402 100.725,26.475 r270 top value=10k
R104 "Resistor" RES_C_0402 99.225,26.475 r270 top value=10k
R106 "Resistor" RES_C_0603 97.775,26.95 r270 top value=0R
R107 "Resistor" RES_C_0402 50.162,78.338 r90 top value=10k
R108 "Resistor" RES_C_0603 49.733,22.504 r90 top value=51R
R109 "Resistor" RES_C_0603 48.831,77.969 r90 top value=0R
R110 "Resistor" RES_C_0603 56.4,78.6 r90 top value=0R
R111 "Resistor" RES_C_0402 57.6,22.1 r0 bottom value=10k
R112 "Resistor" RES_C_0402 52.1,22.8 r0 bottom value=12k
R113 "Resistor" RES_C_0402 50,27.4 r180 top value=10k
R114 "Resistor" RES_C_0805 41.9,92.2 r180 bottom value=62R
R115 "Resistor" RES_C_0805 53.3,92.2 r180 bottom value=62R
R116 "Resistor" RES_C_0805 40.1,89.4 r90 bottom value=62R
R117 "Resistor" RES_C_0805 43.7,89.4 r270 bottom value=62R
R118 "Resistor" RES_C_0805 51.5,89.5 r90 bottom value=62R
R119 "Resistor" RES_C_0805 55.1,89.5 r270 bottom value=62R
R120 "Resistor" RES_C_0402 57,27.1 r270 bottom value=100k
R121 "Resistor" RES_C_0402 54.7,27.1 r270 bottom value=100k
R122 "Resistor" RES_C_0402 53.6,27.1 r270 bottom value=100k
R123 "Resistor" RES_C_0402 52,26.6 r0 bottom value=100k
R124 "Resistor" RES_C_0603 49.5,25.3 r270 top value=1k
R125 "Resistor" RES_C_0603 55.6,6.7 r270 top value=150R
R126 "Resistor" RES_C_0603 73.2,6.7 r270 top value=150R
R127 "Resistor" RES_C_0603 36.5,5.8 r270 top value=150R
R128 "Resistor" RES_C_0603 54.06,6.71 r270 top value=150R
R129 "Resistor" RES_C_0402 74.652,2.374 r90 top value=200k
R130 "Resistor" RES_C_0402 75.227,4.024 r0 top value=100k
R131 "Resistor" RES_C_0402 34.2,31.2 r90 top value=10k
R132 "Resistor" RES_C_0402 34.2,33.155 r0 top value=10k
R133 "Resistor" RES_C_0402 33.9,39.855 r0 top value=12k
R134 "Resistor" RES_C_0402 22.203,30.9 r180 bottom value=10k
R135 "Resistor" RES_C_0603 30.5,41.955 r270 top value=51R
R136 "Resistor" RES_C_0603 3,51.8 r0 bottom value=1k
R137 "Resistor" RES_C_0603 29,41.955 r90 top value=1k
R138 "Resistor" RES_C_0603 27.5,41.955 r90 top value=2.2k
R139 "Resistor" RES_C_0402 25.5,41.2 r270 top value=2k
R140 "Resistor" RES_C_0603 123.8,45.9 r180 bottom value=0R
R141 "Resistor" RES_C_0603 123.8,44.6 r180 bottom value=0R
R142 "Resistor" RES_C_0603 123.8,45.9 r180 top value=0R
R143 "Resistor" RES_C_0603 123.8,44.6 r180 top value=0R
R144 "Resistor" RES_C_0603 9,27.9 r180 bottom value=68R
R145 "Resistor" RES_C_0603 9,45.5 r180 bottom value=68R
R146 "Resistor" RES_C_0402 30.9,62.9 r270 top value=0R
R147 "Resistor" RES_C_0402 29.7,62.9 r270 top value=0R
R148 "Resistor" RES_C_0603 27.6,62.6 r0 top value=51R
R149 "Resistor" RES_C_0402 27.6,60.8 r180 bottom value=6.04k
R150 "Resistor" RES_C_0402 22.203,29.8 r180 bottom value=10k
R151 "Resistor" RES_C_0402 22.2,28.7 r180 bottom value=10k
R152 "Resistor" RES_C_0603 32.6,45.155 r180 top value=1k
R153 "Resistor" RES_C_0402 40.1,56.2 r180 bottom value=10k
R155 "Resistor" RES_C_0402 29,48.6 r180 top value=4.7k
R156 "Resistor" RES_C_0402 28.9,48.6 r0 bottom value=4.7k
R157 "Resistor" RES_C_0402 28.2,50 r180 bottom value=4.7k
R158 "Resistor" RES_C_0603 3,80.9 r0 bottom value=330R
R159 "Resistor" RES_C_0603 3,68.3 r0 bottom value=330R
R160 "Resistor" RES_C_0603 3,61.9 r0 bottom value=330R
R161 "Resistor" RES_C_0603 3.1,49.3 r180 bottom value=330R
R162 "Resistor" RES_C_1206 17.9,65.1 r180 bottom value=0R
R164 "Resistor" RES_C_0603 140,39 r0 bottom value=1k
R165 "Resistor" RES_C_0402 116.9,62.4 r180 top value=0R
R166 "Resistor" RES_C_0402 57.7,37.1 r0 top value=0R
R167 "Resistor" RES_C_0402 105.5,41 r90 top value=10k
R168 "Resistor" RES_C_0603 116.25,56.1 r270 top value=51R
R169 "Resistor" RES_C_0402 114.9,55.9 r270 top value=0R
R170 "Resistor" RES_C_0402 113.7,55.9 r270 top value=0R
R171 "Resistor" RES_C_0402 111.15,41.875 r270 top value=10k
R172 "Resistor" RES_C_0402 113.8,42.9 r90 top value=10k
R173 "Resistor" RES_C_0603 112.5,42.2 r90 top value=1k
R174 "Resistor" RES_C_0402 115.6,48.3 r180 bottom value=12.1k
R175 "Resistor" RES_C_0402 111.2,55.9 r270 top value=10k
R176 "Resistor" RES_C_0402 113.8,41.4 r0 bottom value=4.7k
R177 "Resistor" RES_C_0402 40.1,57.4 r0 bottom value=10k
R178 "Resistor" RES_C_0402 88.1,51.1 r0 bottom value=100k
R179 "Resistor" RES_C_0402 111.6,41.4 r180 bottom value=4.7k
R180 "Resistor" RES_C_0402 111.2,53.1 r270 bottom value=10k
R181 "Resistor" RES_C_0402 110,53.1 r270 bottom value=10k
R182 "Resistor" RES_C_0402 127.1,46.2 r90 bottom value=49.9R
R183 "Resistor" RES_C_0603 123.8,55.8 r180 bottom value=0R
R184 "Resistor" RES_C_0402 88,54.5 r0 bottom value=0R
R185 "Resistor" RES_C_0402 57.7,38.7 r0 top value=0R
R188 "Resistor" RES_C_0402 127.1,44.3 r270 bottom value=49.9R
R189 "Resistor" RES_C_0603 123.8,57.2 r180 bottom value=0R
R190 "Resistor" RES_C_0402 127.1,46.2 r90 top value=49.9R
